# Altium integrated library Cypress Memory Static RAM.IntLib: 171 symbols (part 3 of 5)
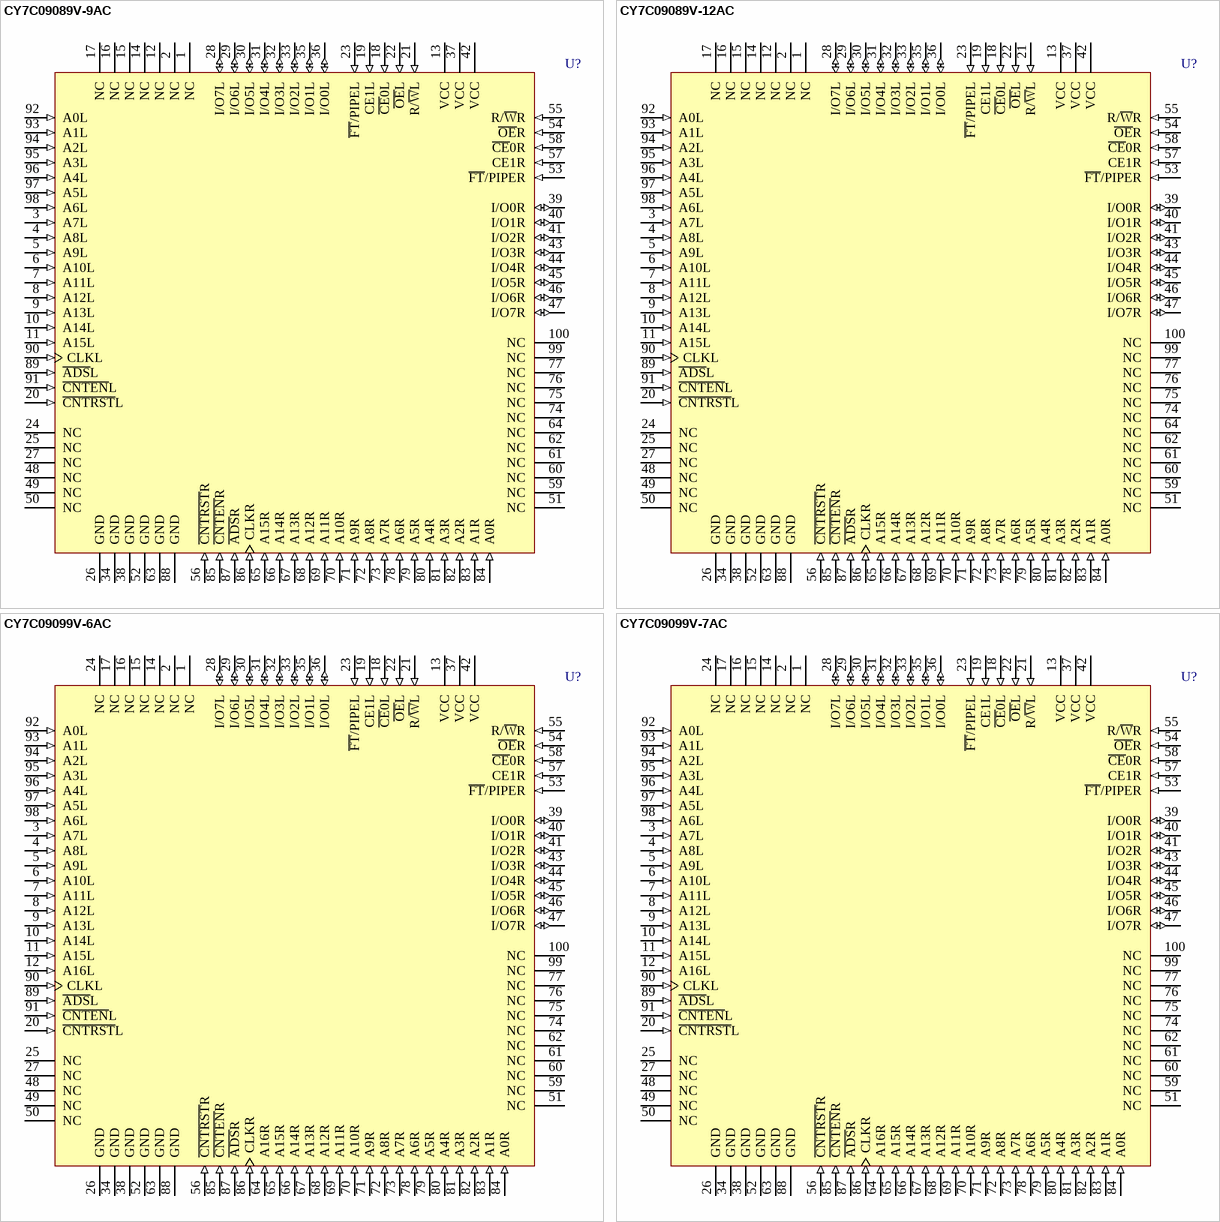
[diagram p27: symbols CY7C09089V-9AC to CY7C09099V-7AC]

## CY7C09099V-6AC
designator U?
3.3V 128K x 8 Synchronous Dual-Port Static RAM
footprint A100_N (Thin QFP, 100-Leads, Body 14x14mm, Pitch 0.5mm, IPC Medium Density)
footprint A100_L (Thin QFP, 100-Leads, Body 14x14mm, Pitch 0.5mm, IPC High Density)
footprint A100_M (Thin QFP, 100-Leads, Body 14x14mm, Pitch 0.5mm, IPC Low Density)
3D model CY7C09099V-A100 (100-Pin Thin Quad Flat Pack 0.5 mm Pitch)
pins: 1 NC, 2 NC, 3 A7L (in), 4 A8L (in), 5 A9L (in), 6 A10L (in), 7 A11L (in), 8 A12L (in), 9 A13L (in), 10 A14L (in), 11 A15L (in), 12 A16L (in), 13 VCC (power), 14 NC, 15 NC, 16 NC, 17 NC, 18 ~{CE}0L (in), 19 CE1L (in), 20 ~{CNTRST}L (in), 21 R/~{W}L (in), 22 ~{OE}L (in), 23 ~{FT}/PIPEL (in), 24 NC, 25 NC, 26 GND (power), 27 NC, 28 I/O7L (io), 29 I/O6L (io), 30 I/O5L (io), 31 I/O4L (io), 32 I/O3L (io), 33 I/O2L (io), 34 GND (power), 35 I/O1L (io), 36 I/O0L (io), 37 VCC (power), 38 GND (power), 39 I/O0R (io), 40 I/O1R (io), 41 I/O2R (io), 42 VCC (power), 43 I/O3R (io), 44 I/O4R (io), 45 I/O5R (io), 46 I/O6R (io), 47 I/O7R (io), 48 NC, 49 NC, 50 NC, 51 NC, 52 GND (power), 53 ~{FT}/PIPER (in), 54 ~{OE}R (in), 55 R/~{W}R (in), 56 ~{CNTRST}R (in), 57 CE1R (in), 58 ~{CE}0R (in), 59 NC, 60 NC, 61 NC, 62 NC, 63 GND (power), 64 A16R (in), 65 A15R (in), 66 A14R (in), 67 A13R (in), 68 A12R (in), 69 A11R (in), 70 A10R (in), 71 A9R (in), 72 A8R (in), 73 A7R (in), 74 NC, 75 NC, 76 NC, 77 NC, 78 A6R (in), 79 A5R (in), 80 A4R (in), 81 A3R (in), 82 A2R (in), 83 A1R (in), 84 A0R (in), 85 ~{CNTEN}R (in), 86 CLKR (in), 87 ~{ADS}R (in), 88 GND (power), 89 ~{ADS}L (in), 90 CLKL (in), 91 ~{CNTEN}L (in), 92 A0L (in), 93 A1L (in), 94 A2L (in), 95 A3L (in), 96 A4L (in), 97 A5L (in), 98 A6L (in), 99 NC, 100 NC

## CY7C09099V-7AC
designator U?
3.3V 128K x 8 Synchronous Dual-Port Static RAM
footprint A100_N (Thin QFP, 100-Leads, Body 14x14mm, Pitch 0.5mm, IPC Medium Density)
footprint A100_L (Thin QFP, 100-Leads, Body 14x14mm, Pitch 0.5mm, IPC High Density)
footprint A100_M (Thin QFP, 100-Leads, Body 14x14mm, Pitch 0.5mm, IPC Low Density)
3D model CY7C09099V-A100 (100-Pin Thin Quad Flat Pack 0.5 mm Pitch)
pins: 1 NC, 2 NC, 3 A7L (in), 4 A8L (in), 5 A9L (in), 6 A10L (in), 7 A11L (in), 8 A12L (in), 9 A13L (in), 10 A14L (in), 11 A15L (in), 12 A16L (in), 13 VCC (power), 14 NC, 15 NC, 16 NC, 17 NC, 18 ~{CE}0L (in), 19 CE1L (in), 20 ~{CNTRST}L (in), 21 R/~{W}L (in), 22 ~{OE}L (in), 23 ~{FT}/PIPEL (in), 24 NC, 25 NC, 26 GND (power), 27 NC, 28 I/O7L (io), 29 I/O6L (io), 30 I/O5L (io), 31 I/O4L (io), 32 I/O3L (io), 33 I/O2L (io), 34 GND (power), 35 I/O1L (io), 36 I/O0L (io), 37 VCC (power), 38 GND (power), 39 I/O0R (io), 40 I/O1R (io), 41 I/O2R (io), 42 VCC (power), 43 I/O3R (io), 44 I/O4R (io), 45 I/O5R (io), 46 I/O6R (io), 47 I/O7R (io), 48 NC, 49 NC, 50 NC, 51 NC, 52 GND (power), 53 ~{FT}/PIPER (in), 54 ~{OE}R (in), 55 R/~{W}R (in), 56 ~{CNTRST}R (in), 57 CE1R (in), 58 ~{CE}0R (in), 59 NC, 60 NC, 61 NC, 62 NC, 63 GND (power), 64 A16R (in), 65 A15R (in), 66 A14R (in), 67 A13R (in), 68 A12R (in), 69 A11R (in), 70 A10R (in), 71 A9R (in), 72 A8R (in), 73 A7R (in), 74 NC, 75 NC, 76 NC, 77 NC, 78 A6R (in), 79 A5R (in), 80 A4R (in), 81 A3R (in), 82 A2R (in), 83 A1R (in), 84 A0R (in), 85 ~{CNTEN}R (in), 86 CLKR (in), 87 ~{ADS}R (in), 88 GND (power), 89 ~{ADS}L (in), 90 CLKL (in), 91 ~{CNTEN}L (in), 92 A0L (in), 93 A1L (in), 94 A2L (in), 95 A3L (in), 96 A4L (in), 97 A5L (in), 98 A6L (in), 99 NC, 100 NC

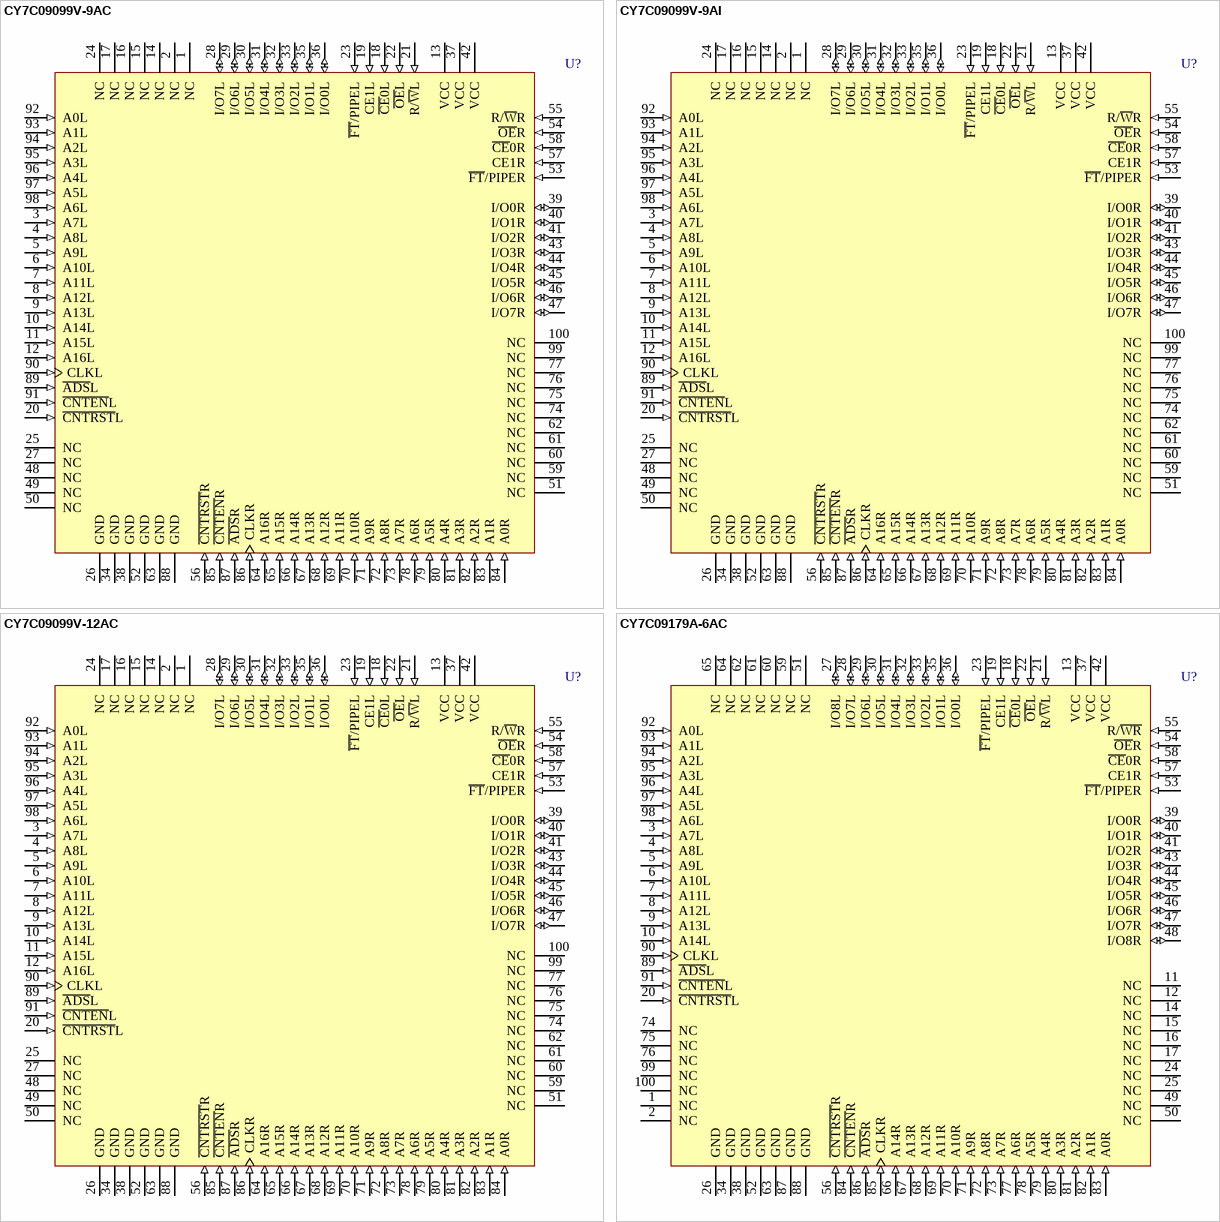
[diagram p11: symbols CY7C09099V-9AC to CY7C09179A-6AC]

## CY7C09099V-9AC
designator U?
3.3V 128K x 8 Synchronous Dual-Port Static RAM
footprint A100_N (Thin QFP, 100-Leads, Body 14x14mm, Pitch 0.5mm, IPC Medium Density)
footprint A100_L (Thin QFP, 100-Leads, Body 14x14mm, Pitch 0.5mm, IPC High Density)
footprint A100_M (Thin QFP, 100-Leads, Body 14x14mm, Pitch 0.5mm, IPC Low Density)
3D model CY7C09099V-A100 (100-Pin Thin Quad Flat Pack 0.5 mm Pitch)
pins: 1 NC, 2 NC, 3 A7L (in), 4 A8L (in), 5 A9L (in), 6 A10L (in), 7 A11L (in), 8 A12L (in), 9 A13L (in), 10 A14L (in), 11 A15L (in), 12 A16L (in), 13 VCC (power), 14 NC, 15 NC, 16 NC, 17 NC, 18 ~{CE}0L (in), 19 CE1L (in), 20 ~{CNTRST}L (in), 21 R/~{W}L (in), 22 ~{OE}L (in), 23 ~{FT}/PIPEL (in), 24 NC, 25 NC, 26 GND (power), 27 NC, 28 I/O7L (io), 29 I/O6L (io), 30 I/O5L (io), 31 I/O4L (io), 32 I/O3L (io), 33 I/O2L (io), 34 GND (power), 35 I/O1L (io), 36 I/O0L (io), 37 VCC (power), 38 GND (power), 39 I/O0R (io), 40 I/O1R (io), 41 I/O2R (io), 42 VCC (power), 43 I/O3R (io), 44 I/O4R (io), 45 I/O5R (io), 46 I/O6R (io), 47 I/O7R (io), 48 NC, 49 NC, 50 NC, 51 NC, 52 GND (power), 53 ~{FT}/PIPER (in), 54 ~{OE}R (in), 55 R/~{W}R (in), 56 ~{CNTRST}R (in), 57 CE1R (in), 58 ~{CE}0R (in), 59 NC, 60 NC, 61 NC, 62 NC, 63 GND (power), 64 A16R (in), 65 A15R (in), 66 A14R (in), 67 A13R (in), 68 A12R (in), 69 A11R (in), 70 A10R (in), 71 A9R (in), 72 A8R (in), 73 A7R (in), 74 NC, 75 NC, 76 NC, 77 NC, 78 A6R (in), 79 A5R (in), 80 A4R (in), 81 A3R (in), 82 A2R (in), 83 A1R (in), 84 A0R (in), 85 ~{CNTEN}R (in), 86 CLKR (in), 87 ~{ADS}R (in), 88 GND (power), 89 ~{ADS}L (in), 90 CLKL (in), 91 ~{CNTEN}L (in), 92 A0L (in), 93 A1L (in), 94 A2L (in), 95 A3L (in), 96 A4L (in), 97 A5L (in), 98 A6L (in), 99 NC, 100 NC

## CY7C09099V-9AI
designator U?
3.3V 128K x 8 Synchronous Dual-Port Static RAM
footprint A100_N (Thin QFP, 100-Leads, Body 14x14mm, Pitch 0.5mm, IPC Medium Density)
footprint A100_L (Thin QFP, 100-Leads, Body 14x14mm, Pitch 0.5mm, IPC High Density)
footprint A100_M (Thin QFP, 100-Leads, Body 14x14mm, Pitch 0.5mm, IPC Low Density)
3D model CY7C09099V-A100 (100-Pin Thin Quad Flat Pack 0.5 mm Pitch)
pins: 1 NC, 2 NC, 3 A7L (in), 4 A8L (in), 5 A9L (in), 6 A10L (in), 7 A11L (in), 8 A12L (in), 9 A13L (in), 10 A14L (in), 11 A15L (in), 12 A16L (in), 13 VCC (power), 14 NC, 15 NC, 16 NC, 17 NC, 18 ~{CE}0L (in), 19 CE1L (in), 20 ~{CNTRST}L (in), 21 R/~{W}L (in), 22 ~{OE}L (in), 23 ~{FT}/PIPEL (in), 24 NC, 25 NC, 26 GND (power), 27 NC, 28 I/O7L (io), 29 I/O6L (io), 30 I/O5L (io), 31 I/O4L (io), 32 I/O3L (io), 33 I/O2L (io), 34 GND (power), 35 I/O1L (io), 36 I/O0L (io), 37 VCC (power), 38 GND (power), 39 I/O0R (io), 40 I/O1R (io), 41 I/O2R (io), 42 VCC (power), 43 I/O3R (io), 44 I/O4R (io), 45 I/O5R (io), 46 I/O6R (io), 47 I/O7R (io), 48 NC, 49 NC, 50 NC, 51 NC, 52 GND (power), 53 ~{FT}/PIPER (in), 54 ~{OE}R (in), 55 R/~{W}R (in), 56 ~{CNTRST}R (in), 57 CE1R (in), 58 ~{CE}0R (in), 59 NC, 60 NC, 61 NC, 62 NC, 63 GND (power), 64 A16R (in), 65 A15R (in), 66 A14R (in), 67 A13R (in), 68 A12R (in), 69 A11R (in), 70 A10R (in), 71 A9R (in), 72 A8R (in), 73 A7R (in), 74 NC, 75 NC, 76 NC, 77 NC, 78 A6R (in), 79 A5R (in), 80 A4R (in), 81 A3R (in), 82 A2R (in), 83 A1R (in), 84 A0R (in), 85 ~{CNTEN}R (in), 86 CLKR (in), 87 ~{ADS}R (in), 88 GND (power), 89 ~{ADS}L (in), 90 CLKL (in), 91 ~{CNTEN}L (in), 92 A0L (in), 93 A1L (in), 94 A2L (in), 95 A3L (in), 96 A4L (in), 97 A5L (in), 98 A6L (in), 99 NC, 100 NC

## CY7C09099V-12AC
designator U?
3.3V 128K x 8 Synchronous Dual-Port Static RAM
footprint A100_N (Thin QFP, 100-Leads, Body 14x14mm, Pitch 0.5mm, IPC Medium Density)
footprint A100_L (Thin QFP, 100-Leads, Body 14x14mm, Pitch 0.5mm, IPC High Density)
footprint A100_M (Thin QFP, 100-Leads, Body 14x14mm, Pitch 0.5mm, IPC Low Density)
3D model CY7C09099V-A100 (100-Pin Thin Quad Flat Pack 0.5 mm Pitch)
pins: 1 NC, 2 NC, 3 A7L (in), 4 A8L (in), 5 A9L (in), 6 A10L (in), 7 A11L (in), 8 A12L (in), 9 A13L (in), 10 A14L (in), 11 A15L (in), 12 A16L (in), 13 VCC (power), 14 NC, 15 NC, 16 NC, 17 NC, 18 ~{CE}0L (in), 19 CE1L (in), 20 ~{CNTRST}L (in), 21 R/~{W}L (in), 22 ~{OE}L (in), 23 ~{FT}/PIPEL (in), 24 NC, 25 NC, 26 GND (power), 27 NC, 28 I/O7L (io), 29 I/O6L (io), 30 I/O5L (io), 31 I/O4L (io), 32 I/O3L (io), 33 I/O2L (io), 34 GND (power), 35 I/O1L (io), 36 I/O0L (io), 37 VCC (power), 38 GND (power), 39 I/O0R (io), 40 I/O1R (io), 41 I/O2R (io), 42 VCC (power), 43 I/O3R (io), 44 I/O4R (io), 45 I/O5R (io), 46 I/O6R (io), 47 I/O7R (io), 48 NC, 49 NC, 50 NC, 51 NC, 52 GND (power), 53 ~{FT}/PIPER (in), 54 ~{OE}R (in), 55 R/~{W}R (in), 56 ~{CNTRST}R (in), 57 CE1R (in), 58 ~{CE}0R (in), 59 NC, 60 NC, 61 NC, 62 NC, 63 GND (power), 64 A16R (in), 65 A15R (in), 66 A14R (in), 67 A13R (in), 68 A12R (in), 69 A11R (in), 70 A10R (in), 71 A9R (in), 72 A8R (in), 73 A7R (in), 74 NC, 75 NC, 76 NC, 77 NC, 78 A6R (in), 79 A5R (in), 80 A4R (in), 81 A3R (in), 82 A2R (in), 83 A1R (in), 84 A0R (in), 85 ~{CNTEN}R (in), 86 CLKR (in), 87 ~{ADS}R (in), 88 GND (power), 89 ~{ADS}L (in), 90 CLKL (in), 91 ~{CNTEN}L (in), 92 A0L (in), 93 A1L (in), 94 A2L (in), 95 A3L (in), 96 A4L (in), 97 A5L (in), 98 A6L (in), 99 NC, 100 NC

## CY7C09179A-6AC
designator U?
32K x 9 Synchronous Dual-Port RAM
footprint A100_N (Thin QFP, 100-Leads, Body 14x14mm, Pitch 0.5mm, IPC Medium Density)
footprint A100_L (Thin QFP, 100-Leads, Body 14x14mm, Pitch 0.5mm, IPC High Density)
footprint A100_M (Thin QFP, 100-Leads, Body 14x14mm, Pitch 0.5mm, IPC Low Density)
3D model CY7C09179A-A100 (100-Pin Thin Quad Flat Pack 0.5 mm Pitch)
pins: 1 NC, 2 NC, 3 A7L (in), 4 A8L (in), 5 A9L (in), 6 A10L (in), 7 A11L (in), 8 A12L (in), 9 A13L (in), 10 A14L (in), 11 NC, 12 NC, 13 VCC (power), 14 NC, 15 NC, 16 NC, 17 NC, 18 ~{CE}0L (in), 19 CE1L (in), 20 ~{CNTRST}L (in), 21 R/~{W}L (in), 22 ~{OE}L (in), 23 ~{FT}/PIPEL (in), 24 NC, 25 NC, 26 GND (power), 27 I/O8L (io), 28 I/O7L (io), 29 I/O6L (io), 30 I/O5L (io), 31 I/O4L (io), 32 I/O3L (io), 33 I/O2L (io), 34 GND (power), 35 I/O1L (io), 36 I/O0L (io), 37 VCC (power), 38 GND (power), 39 I/O0R (io), 40 I/O1R (io), 41 I/O2R (io), 42 VCC (power), 43 I/O3R (io), 44 I/O4R (io), 45 I/O5R (io), 46 I/O6R (io), 47 I/O7R (io), 48 I/O8R (io), 49 NC, 50 NC, 51 NC, 52 GND (power), 53 ~{FT}/PIPER (in), 54 ~{OE}R (in), 55 R/~{WR} (in), 56 ~{CNTRST}R (in), 57 CE1R (in), 58 ~{CE}0R (in), 59 NC, 60 NC, 61 NC, 62 NC, 63 GND (power), 64 NC, 65 NC, 66 A14R (in), 67 A13R (in), 68 A12R (in), 69 A11R (in), 70 A10R (in), 71 A9R (in), 72 A8R (in), 73 A7R (in), 74 NC, 75 NC, 76 NC, 77 A6R (in), 78 A5R (in), 79 A4R (in), 80 A3R (in), 81 A2R (in), 82 A1R (in), 83 A0R (in), 84 ~{CNTEN}R (in), 85 CLKR (in), 86 ~{ADS}R (in), 87 GND (power), 88 GND (power), 89 ~{ADS}L (in), 90 CLKL (in), 91 ~{CNTEN}L (in), 92 A0L (in), 93 A1L (in), 94 A2L (in), 95 A3L (in), 96 A4L (in), 97 A5L (in), 98 A6L (in), 99 NC, 100 NC

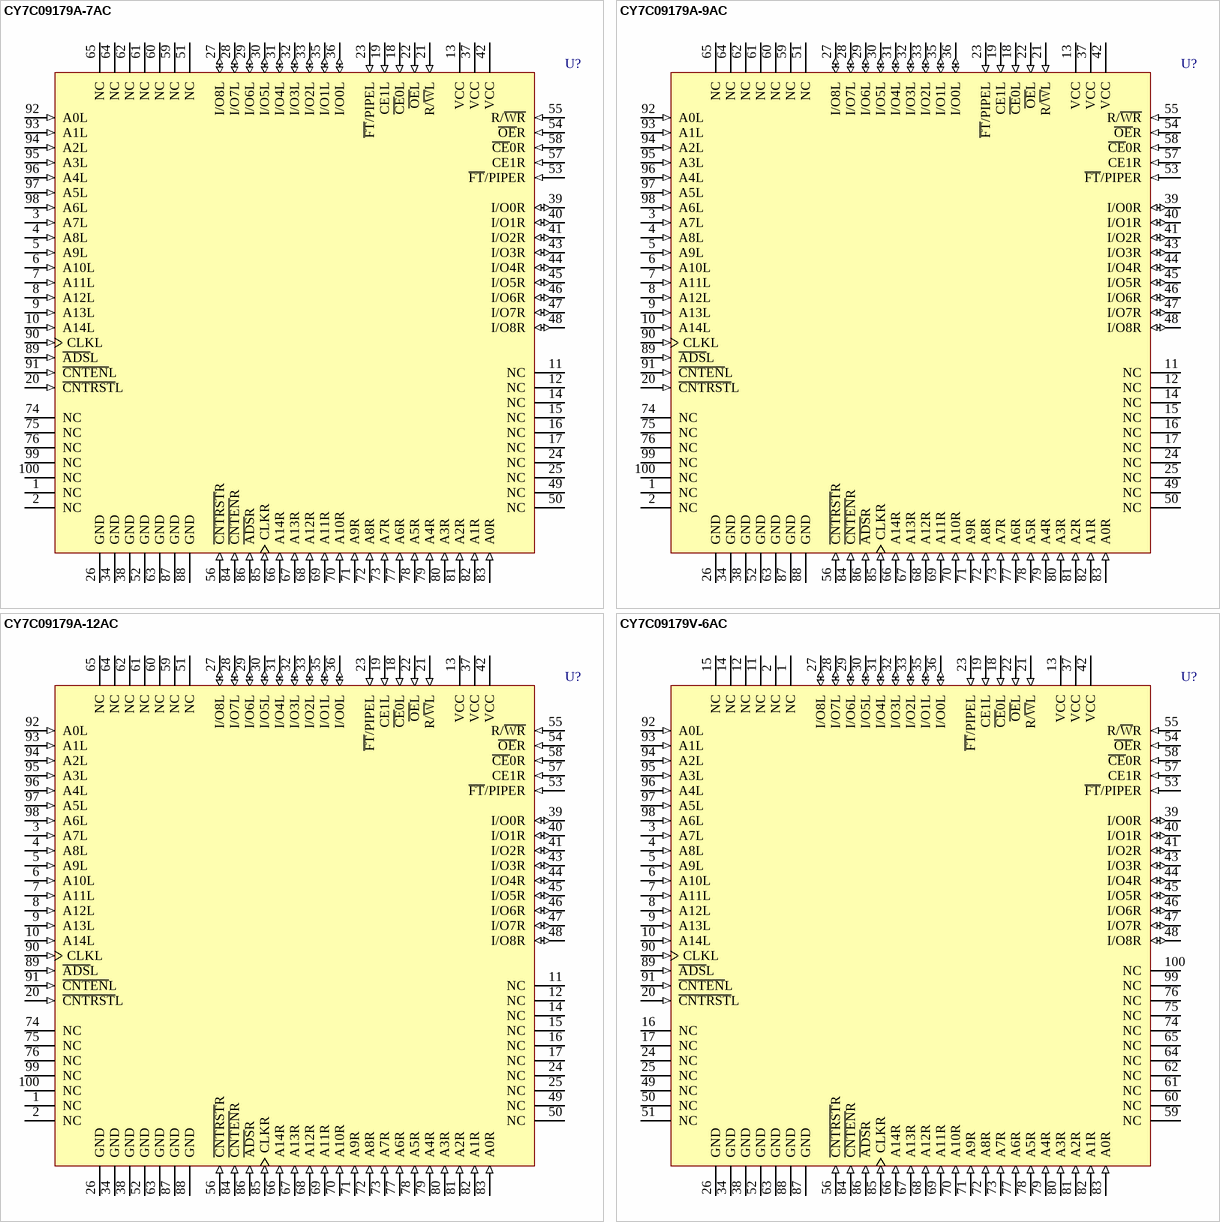
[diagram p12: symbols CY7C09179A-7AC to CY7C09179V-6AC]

## CY7C09179A-7AC
designator U?
32K x 9 Synchronous Dual-Port RAM
footprint A100_N (Thin QFP, 100-Leads, Body 14x14mm, Pitch 0.5mm, IPC Medium Density)
footprint A100_L (Thin QFP, 100-Leads, Body 14x14mm, Pitch 0.5mm, IPC High Density)
footprint A100_M (Thin QFP, 100-Leads, Body 14x14mm, Pitch 0.5mm, IPC Low Density)
3D model CY7C09179A-A100 (100-Pin Thin Quad Flat Pack 0.5 mm Pitch)
pins: 1 NC, 2 NC, 3 A7L (in), 4 A8L (in), 5 A9L (in), 6 A10L (in), 7 A11L (in), 8 A12L (in), 9 A13L (in), 10 A14L (in), 11 NC, 12 NC, 13 VCC (power), 14 NC, 15 NC, 16 NC, 17 NC, 18 ~{CE}0L (in), 19 CE1L (in), 20 ~{CNTRST}L (in), 21 R/~{W}L (in), 22 ~{OE}L (in), 23 ~{FT}/PIPEL (in), 24 NC, 25 NC, 26 GND (power), 27 I/O8L (io), 28 I/O7L (io), 29 I/O6L (io), 30 I/O5L (io), 31 I/O4L (io), 32 I/O3L (io), 33 I/O2L (io), 34 GND (power), 35 I/O1L (io), 36 I/O0L (io), 37 VCC (power), 38 GND (power), 39 I/O0R (io), 40 I/O1R (io), 41 I/O2R (io), 42 VCC (power), 43 I/O3R (io), 44 I/O4R (io), 45 I/O5R (io), 46 I/O6R (io), 47 I/O7R (io), 48 I/O8R (io), 49 NC, 50 NC, 51 NC, 52 GND (power), 53 ~{FT}/PIPER (in), 54 ~{OE}R (in), 55 R/~{WR} (in), 56 ~{CNTRST}R (in), 57 CE1R (in), 58 ~{CE}0R (in), 59 NC, 60 NC, 61 NC, 62 NC, 63 GND (power), 64 NC, 65 NC, 66 A14R (in), 67 A13R (in), 68 A12R (in), 69 A11R (in), 70 A10R (in), 71 A9R (in), 72 A8R (in), 73 A7R (in), 74 NC, 75 NC, 76 NC, 77 A6R (in), 78 A5R (in), 79 A4R (in), 80 A3R (in), 81 A2R (in), 82 A1R (in), 83 A0R (in), 84 ~{CNTEN}R (in), 85 CLKR (in), 86 ~{ADS}R (in), 87 GND (power), 88 GND (power), 89 ~{ADS}L (in), 90 CLKL (in), 91 ~{CNTEN}L (in), 92 A0L (in), 93 A1L (in), 94 A2L (in), 95 A3L (in), 96 A4L (in), 97 A5L (in), 98 A6L (in), 99 NC, 100 NC

## CY7C09179A-9AC
designator U?
32K x 9 Synchronous Dual-Port RAM
footprint A100_N (Thin QFP, 100-Leads, Body 14x14mm, Pitch 0.5mm, IPC Medium Density)
footprint A100_L (Thin QFP, 100-Leads, Body 14x14mm, Pitch 0.5mm, IPC High Density)
footprint A100_M (Thin QFP, 100-Leads, Body 14x14mm, Pitch 0.5mm, IPC Low Density)
3D model CY7C09179A-A100 (100-Pin Thin Quad Flat Pack 0.5 mm Pitch)
pins: 1 NC, 2 NC, 3 A7L (in), 4 A8L (in), 5 A9L (in), 6 A10L (in), 7 A11L (in), 8 A12L (in), 9 A13L (in), 10 A14L (in), 11 NC, 12 NC, 13 VCC (power), 14 NC, 15 NC, 16 NC, 17 NC, 18 ~{CE}0L (in), 19 CE1L (in), 20 ~{CNTRST}L (in), 21 R/~{W}L (in), 22 ~{OE}L (in), 23 ~{FT}/PIPEL (in), 24 NC, 25 NC, 26 GND (power), 27 I/O8L (io), 28 I/O7L (io), 29 I/O6L (io), 30 I/O5L (io), 31 I/O4L (io), 32 I/O3L (io), 33 I/O2L (io), 34 GND (power), 35 I/O1L (io), 36 I/O0L (io), 37 VCC (power), 38 GND (power), 39 I/O0R (io), 40 I/O1R (io), 41 I/O2R (io), 42 VCC (power), 43 I/O3R (io), 44 I/O4R (io), 45 I/O5R (io), 46 I/O6R (io), 47 I/O7R (io), 48 I/O8R (io), 49 NC, 50 NC, 51 NC, 52 GND (power), 53 ~{FT}/PIPER (in), 54 ~{OE}R (in), 55 R/~{WR} (in), 56 ~{CNTRST}R (in), 57 CE1R (in), 58 ~{CE}0R (in), 59 NC, 60 NC, 61 NC, 62 NC, 63 GND (power), 64 NC, 65 NC, 66 A14R (in), 67 A13R (in), 68 A12R (in), 69 A11R (in), 70 A10R (in), 71 A9R (in), 72 A8R (in), 73 A7R (in), 74 NC, 75 NC, 76 NC, 77 A6R (in), 78 A5R (in), 79 A4R (in), 80 A3R (in), 81 A2R (in), 82 A1R (in), 83 A0R (in), 84 ~{CNTEN}R (in), 85 CLKR (in), 86 ~{ADS}R (in), 87 GND (power), 88 GND (power), 89 ~{ADS}L (in), 90 CLKL (in), 91 ~{CNTEN}L (in), 92 A0L (in), 93 A1L (in), 94 A2L (in), 95 A3L (in), 96 A4L (in), 97 A5L (in), 98 A6L (in), 99 NC, 100 NC

## CY7C09179A-12AC
designator U?
32K x 9 Synchronous Dual-Port RAM
footprint A100_N (Thin QFP, 100-Leads, Body 14x14mm, Pitch 0.5mm, IPC Medium Density)
footprint A100_L (Thin QFP, 100-Leads, Body 14x14mm, Pitch 0.5mm, IPC High Density)
footprint A100_M (Thin QFP, 100-Leads, Body 14x14mm, Pitch 0.5mm, IPC Low Density)
3D model CY7C09179A-A100 (100-Pin Thin Quad Flat Pack 0.5 mm Pitch)
pins: 1 NC, 2 NC, 3 A7L (in), 4 A8L (in), 5 A9L (in), 6 A10L (in), 7 A11L (in), 8 A12L (in), 9 A13L (in), 10 A14L (in), 11 NC, 12 NC, 13 VCC (power), 14 NC, 15 NC, 16 NC, 17 NC, 18 ~{CE}0L (in), 19 CE1L (in), 20 ~{CNTRST}L (in), 21 R/~{W}L (in), 22 ~{OE}L (in), 23 ~{FT}/PIPEL (in), 24 NC, 25 NC, 26 GND (power), 27 I/O8L (io), 28 I/O7L (io), 29 I/O6L (io), 30 I/O5L (io), 31 I/O4L (io), 32 I/O3L (io), 33 I/O2L (io), 34 GND (power), 35 I/O1L (io), 36 I/O0L (io), 37 VCC (power), 38 GND (power), 39 I/O0R (io), 40 I/O1R (io), 41 I/O2R (io), 42 VCC (power), 43 I/O3R (io), 44 I/O4R (io), 45 I/O5R (io), 46 I/O6R (io), 47 I/O7R (io), 48 I/O8R (io), 49 NC, 50 NC, 51 NC, 52 GND (power), 53 ~{FT}/PIPER (in), 54 ~{OE}R (in), 55 R/~{WR} (in), 56 ~{CNTRST}R (in), 57 CE1R (in), 58 ~{CE}0R (in), 59 NC, 60 NC, 61 NC, 62 NC, 63 GND (power), 64 NC, 65 NC, 66 A14R (in), 67 A13R (in), 68 A12R (in), 69 A11R (in), 70 A10R (in), 71 A9R (in), 72 A8R (in), 73 A7R (in), 74 NC, 75 NC, 76 NC, 77 A6R (in), 78 A5R (in), 79 A4R (in), 80 A3R (in), 81 A2R (in), 82 A1R (in), 83 A0R (in), 84 ~{CNTEN}R (in), 85 CLKR (in), 86 ~{ADS}R (in), 87 GND (power), 88 GND (power), 89 ~{ADS}L (in), 90 CLKL (in), 91 ~{CNTEN}L (in), 92 A0L (in), 93 A1L (in), 94 A2L (in), 95 A3L (in), 96 A4L (in), 97 A5L (in), 98 A6L (in), 99 NC, 100 NC

## CY7C09179V-6AC
designator U?
3.3V 32K x 9 Synchronous Dual-Port Static RAM
footprint A100_N (Thin QFP, 100-Leads, Body 14x14mm, Pitch 0.5mm, IPC Medium Density)
footprint A100_L (Thin QFP, 100-Leads, Body 14x14mm, Pitch 0.5mm, IPC High Density)
footprint A100_M (Thin QFP, 100-Leads, Body 14x14mm, Pitch 0.5mm, IPC Low Density)
3D model CY7C09179V-A100 (100-Pin Thin Quad Flat Pack 0.5 mm Pitch)
pins: 1 NC, 2 NC, 3 A7L (in), 4 A8L (in), 5 A9L (in), 6 A10L (in), 7 A11L (in), 8 A12L (in), 9 A13L (in), 10 A14L (in), 11 NC, 12 NC, 13 VCC (power), 14 NC, 15 NC, 16 NC, 17 NC, 18 ~{CE}0L (in), 19 CE1L (in), 20 ~{CNTRST}L (in), 21 R/~{W}L (in), 22 ~{OE}L (in), 23 ~{FT}/PIPEL (in), 24 NC, 25 NC, 26 GND (power), 27 I/O8L (io), 28 I/O7L (io), 29 I/O6L (io), 30 I/O5L (io), 31 I/O4L (io), 32 I/O3L (io), 33 I/O2L (io), 34 GND (power), 35 I/O1L (io), 36 I/O0L (io), 37 VCC (power), 38 GND (power), 39 I/O0R (io), 40 I/O1R (io), 41 I/O2R (io), 42 VCC (power), 43 I/O3R (io), 44 I/O4R (io), 45 I/O5R (io), 46 I/O6R (io), 47 I/O7R (io), 48 I/O8R (io), 49 NC, 50 NC, 51 NC, 52 GND (power), 53 ~{FT}/PIPER (in), 54 ~{OE}R (in), 55 R/~{W}R (in), 56 ~{CNTRST}R (in), 57 CE1R (in), 58 ~{CE}0R (in), 59 NC, 60 NC, 61 NC, 62 NC, 63 GND (power), 64 NC, 65 NC, 66 A14R (in), 67 A13R (in), 68 A12R (in), 69 A11R (in), 70 A10R (in), 71 A9R (in), 72 A8R (in), 73 A7R (in), 74 NC, 75 NC, 76 NC, 77 A6R (in), 78 A5R (in), 79 A4R (in), 80 A3R (in), 81 A2R (in), 82 A1R (in), 83 A0R (in), 84 ~{CNTEN}R (in), 85 CLKR (in), 86 ~{ADS}R (in), 87 GND (power), 88 GND (power), 89 ~{ADS}L (in), 90 CLKL (in), 91 ~{CNTEN}L (in), 92 A0L (in), 93 A1L (in), 94 A2L (in), 95 A3L (in), 96 A4L (in), 97 A5L (in), 98 A6L (in), 99 NC, 100 NC

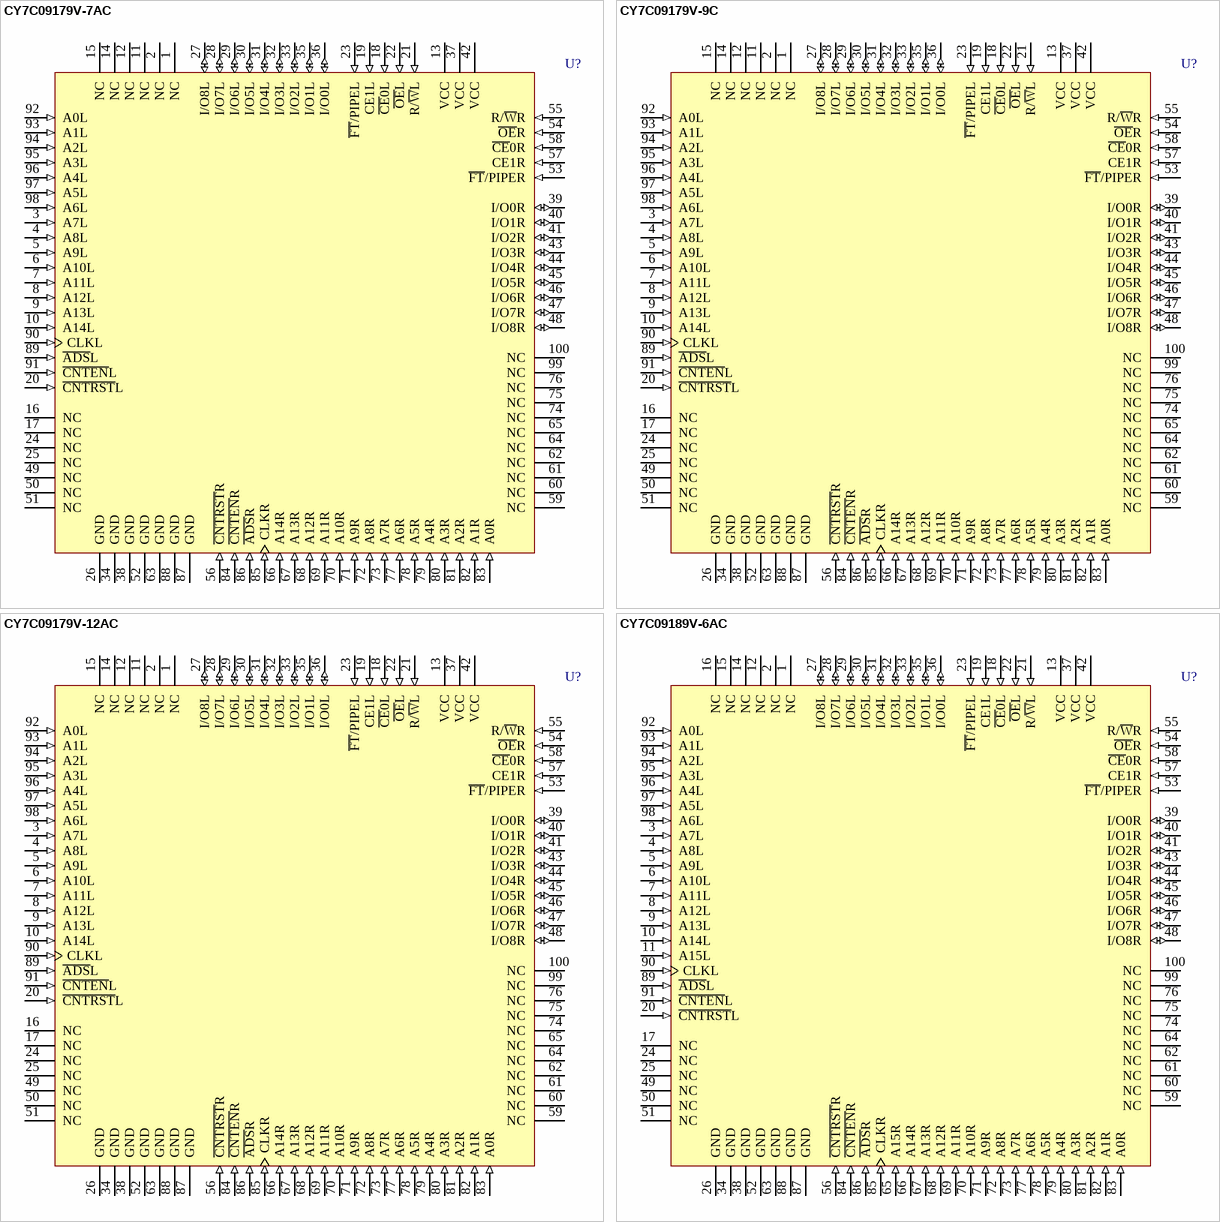
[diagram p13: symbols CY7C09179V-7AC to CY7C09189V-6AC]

## CY7C09179V-7AC
designator U?
3.3V 32K x 9 Synchronous Dual-Port Static RAM
footprint A100_N (Thin QFP, 100-Leads, Body 14x14mm, Pitch 0.5mm, IPC Medium Density)
footprint A100_L (Thin QFP, 100-Leads, Body 14x14mm, Pitch 0.5mm, IPC High Density)
footprint A100_M (Thin QFP, 100-Leads, Body 14x14mm, Pitch 0.5mm, IPC Low Density)
3D model CY7C09179V-A100 (100-Pin Thin Quad Flat Pack 0.5 mm Pitch)
pins: 1 NC, 2 NC, 3 A7L (in), 4 A8L (in), 5 A9L (in), 6 A10L (in), 7 A11L (in), 8 A12L (in), 9 A13L (in), 10 A14L (in), 11 NC, 12 NC, 13 VCC (power), 14 NC, 15 NC, 16 NC, 17 NC, 18 ~{CE}0L (in), 19 CE1L (in), 20 ~{CNTRST}L (in), 21 R/~{W}L (in), 22 ~{OE}L (in), 23 ~{FT}/PIPEL (in), 24 NC, 25 NC, 26 GND (power), 27 I/O8L (io), 28 I/O7L (io), 29 I/O6L (io), 30 I/O5L (io), 31 I/O4L (io), 32 I/O3L (io), 33 I/O2L (io), 34 GND (power), 35 I/O1L (io), 36 I/O0L (io), 37 VCC (power), 38 GND (power), 39 I/O0R (io), 40 I/O1R (io), 41 I/O2R (io), 42 VCC (power), 43 I/O3R (io), 44 I/O4R (io), 45 I/O5R (io), 46 I/O6R (io), 47 I/O7R (io), 48 I/O8R (io), 49 NC, 50 NC, 51 NC, 52 GND (power), 53 ~{FT}/PIPER (in), 54 ~{OE}R (in), 55 R/~{W}R (in), 56 ~{CNTRST}R (in), 57 CE1R (in), 58 ~{CE}0R (in), 59 NC, 60 NC, 61 NC, 62 NC, 63 GND (power), 64 NC, 65 NC, 66 A14R (in), 67 A13R (in), 68 A12R (in), 69 A11R (in), 70 A10R (in), 71 A9R (in), 72 A8R (in), 73 A7R (in), 74 NC, 75 NC, 76 NC, 77 A6R (in), 78 A5R (in), 79 A4R (in), 80 A3R (in), 81 A2R (in), 82 A1R (in), 83 A0R (in), 84 ~{CNTEN}R (in), 85 CLKR (in), 86 ~{ADS}R (in), 87 GND (power), 88 GND (power), 89 ~{ADS}L (in), 90 CLKL (in), 91 ~{CNTEN}L (in), 92 A0L (in), 93 A1L (in), 94 A2L (in), 95 A3L (in), 96 A4L (in), 97 A5L (in), 98 A6L (in), 99 NC, 100 NC

## CY7C09179V-9C
designator U?
3.3V 32K x 9 Synchronous Dual-Port Static RAM
footprint A100_N (Thin QFP, 100-Leads, Body 14x14mm, Pitch 0.5mm, IPC Medium Density)
footprint A100_L (Thin QFP, 100-Leads, Body 14x14mm, Pitch 0.5mm, IPC High Density)
footprint A100_M (Thin QFP, 100-Leads, Body 14x14mm, Pitch 0.5mm, IPC Low Density)
3D model CY7C09179V-A100 (100-Pin Thin Quad Flat Pack 0.5 mm Pitch)
pins: 1 NC, 2 NC, 3 A7L (in), 4 A8L (in), 5 A9L (in), 6 A10L (in), 7 A11L (in), 8 A12L (in), 9 A13L (in), 10 A14L (in), 11 NC, 12 NC, 13 VCC (power), 14 NC, 15 NC, 16 NC, 17 NC, 18 ~{CE}0L (in), 19 CE1L (in), 20 ~{CNTRST}L (in), 21 R/~{W}L (in), 22 ~{OE}L (in), 23 ~{FT}/PIPEL (in), 24 NC, 25 NC, 26 GND (power), 27 I/O8L (io), 28 I/O7L (io), 29 I/O6L (io), 30 I/O5L (io), 31 I/O4L (io), 32 I/O3L (io), 33 I/O2L (io), 34 GND (power), 35 I/O1L (io), 36 I/O0L (io), 37 VCC (power), 38 GND (power), 39 I/O0R (io), 40 I/O1R (io), 41 I/O2R (io), 42 VCC (power), 43 I/O3R (io), 44 I/O4R (io), 45 I/O5R (io), 46 I/O6R (io), 47 I/O7R (io), 48 I/O8R (io), 49 NC, 50 NC, 51 NC, 52 GND (power), 53 ~{FT}/PIPER (in), 54 ~{OE}R (in), 55 R/~{W}R (in), 56 ~{CNTRST}R (in), 57 CE1R (in), 58 ~{CE}0R (in), 59 NC, 60 NC, 61 NC, 62 NC, 63 GND (power), 64 NC, 65 NC, 66 A14R (in), 67 A13R (in), 68 A12R (in), 69 A11R (in), 70 A10R (in), 71 A9R (in), 72 A8R (in), 73 A7R (in), 74 NC, 75 NC, 76 NC, 77 A6R (in), 78 A5R (in), 79 A4R (in), 80 A3R (in), 81 A2R (in), 82 A1R (in), 83 A0R (in), 84 ~{CNTEN}R (in), 85 CLKR (in), 86 ~{ADS}R (in), 87 GND (power), 88 GND (power), 89 ~{ADS}L (in), 90 CLKL (in), 91 ~{CNTEN}L (in), 92 A0L (in), 93 A1L (in), 94 A2L (in), 95 A3L (in), 96 A4L (in), 97 A5L (in), 98 A6L (in), 99 NC, 100 NC

## CY7C09179V-12AC
designator U?
3.3V 32K x 9 Synchronous Dual-Port Static RAM
footprint A100_N (Thin QFP, 100-Leads, Body 14x14mm, Pitch 0.5mm, IPC Medium Density)
footprint A100_L (Thin QFP, 100-Leads, Body 14x14mm, Pitch 0.5mm, IPC High Density)
footprint A100_M (Thin QFP, 100-Leads, Body 14x14mm, Pitch 0.5mm, IPC Low Density)
3D model CY7C09179V-A100 (100-Pin Thin Quad Flat Pack 0.5 mm Pitch)
pins: 1 NC, 2 NC, 3 A7L (in), 4 A8L (in), 5 A9L (in), 6 A10L (in), 7 A11L (in), 8 A12L (in), 9 A13L (in), 10 A14L (in), 11 NC, 12 NC, 13 VCC (power), 14 NC, 15 NC, 16 NC, 17 NC, 18 ~{CE}0L (in), 19 CE1L (in), 20 ~{CNTRST}L (in), 21 R/~{W}L (in), 22 ~{OE}L (in), 23 ~{FT}/PIPEL (in), 24 NC, 25 NC, 26 GND (power), 27 I/O8L (io), 28 I/O7L (io), 29 I/O6L (io), 30 I/O5L (io), 31 I/O4L (io), 32 I/O3L (io), 33 I/O2L (io), 34 GND (power), 35 I/O1L (io), 36 I/O0L (io), 37 VCC (power), 38 GND (power), 39 I/O0R (io), 40 I/O1R (io), 41 I/O2R (io), 42 VCC (power), 43 I/O3R (io), 44 I/O4R (io), 45 I/O5R (io), 46 I/O6R (io), 47 I/O7R (io), 48 I/O8R (io), 49 NC, 50 NC, 51 NC, 52 GND (power), 53 ~{FT}/PIPER (in), 54 ~{OE}R (in), 55 R/~{W}R (in), 56 ~{CNTRST}R (in), 57 CE1R (in), 58 ~{CE}0R (in), 59 NC, 60 NC, 61 NC, 62 NC, 63 GND (power), 64 NC, 65 NC, 66 A14R (in), 67 A13R (in), 68 A12R (in), 69 A11R (in), 70 A10R (in), 71 A9R (in), 72 A8R (in), 73 A7R (in), 74 NC, 75 NC, 76 NC, 77 A6R (in), 78 A5R (in), 79 A4R (in), 80 A3R (in), 81 A2R (in), 82 A1R (in), 83 A0R (in), 84 ~{CNTEN}R (in), 85 CLKR (in), 86 ~{ADS}R (in), 87 GND (power), 88 GND (power), 89 ~{ADS}L (in), 90 CLKL (in), 91 ~{CNTEN}L (in), 92 A0L (in), 93 A1L (in), 94 A2L (in), 95 A3L (in), 96 A4L (in), 97 A5L (in), 98 A6L (in), 99 NC, 100 NC

## CY7C09189V-6AC
designator U?
3.3V 64K x 9 Synchronous Dual-Port Static RAM
footprint A100_N (Thin QFP, 100-Leads, Body 14x14mm, Pitch 0.5mm, IPC Medium Density)
footprint A100_L (Thin QFP, 100-Leads, Body 14x14mm, Pitch 0.5mm, IPC High Density)
footprint A100_M (Thin QFP, 100-Leads, Body 14x14mm, Pitch 0.5mm, IPC Low Density)
3D model CY7C09189V-A100 (100-Pin Thin Quad Flat Pack 0.5 mm Pitch)
pins: 1 NC, 2 NC, 3 A7L (in), 4 A8L (in), 5 A9L (in), 6 A10L (in), 7 A11L (in), 8 A12L (in), 9 A13L (in), 10 A14L (in), 11 A15L (in), 12 NC, 13 VCC (power), 14 NC, 15 NC, 16 NC, 17 NC, 18 ~{CE}0L (in), 19 CE1L (in), 20 ~{CNTRST}L (in), 21 R/~{W}L (in), 22 ~{OE}L (in), 23 ~{FT}/PIPEL (in), 24 NC, 25 NC, 26 GND (power), 27 I/O8L (io), 28 I/O7L (io), 29 I/O6L (io), 30 I/O5L (io), 31 I/O4L (io), 32 I/O3L (io), 33 I/O2L (io), 34 GND (power), 35 I/O1L (io), 36 I/O0L (io), 37 VCC (power), 38 GND (power), 39 I/O0R (io), 40 I/O1R (io), 41 I/O2R (io), 42 VCC (power), 43 I/O3R (io), 44 I/O4R (io), 45 I/O5R (io), 46 I/O6R (io), 47 I/O7R (io), 48 I/O8R (io), 49 NC, 50 NC, 51 NC, 52 GND (power), 53 ~{FT}/PIPER (in), 54 ~{OE}R (in), 55 R/~{W}R (in), 56 ~{CNTRST}R (in), 57 CE1R (in), 58 ~{CE}0R (in), 59 NC, 60 NC, 61 NC, 62 NC, 63 GND (power), 64 NC, 65 A15R (in), 66 A14R (in), 67 A13R (in), 68 A12R (in), 69 A11R (in), 70 A10R (in), 71 A9R (in), 72 A8R (in), 73 A7R (in), 74 NC, 75 NC, 76 NC, 77 A6R (in), 78 A5R (in), 79 A4R (in), 80 A3R (in), 81 A2R (in), 82 A1R (in), 83 A0R (in), 84 ~{CNTEN}R (in), 85 CLKR (in), 86 ~{ADS}R (in), 87 GND (power), 88 GND (power), 89 ~{ADS}L (in), 90 CLKL (in), 91 ~{CNTEN}L (in), 92 A0L (in), 93 A1L (in), 94 A2L (in), 95 A3L (in), 96 A4L (in), 97 A5L (in), 98 A6L (in), 99 NC, 100 NC

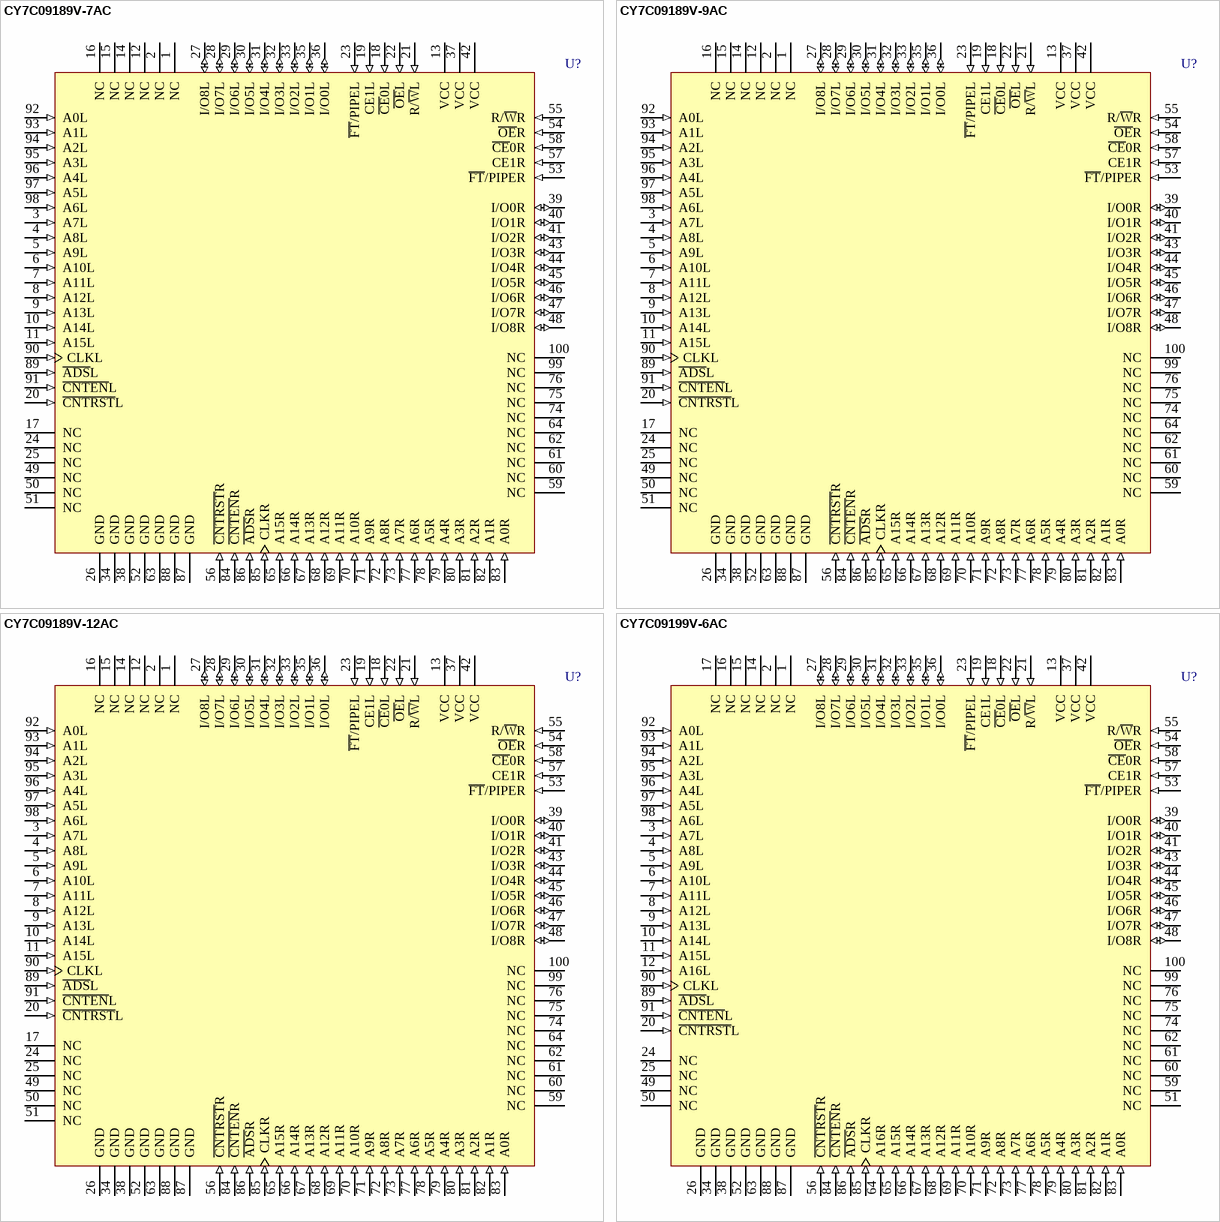
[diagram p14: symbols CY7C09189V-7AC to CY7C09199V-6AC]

## CY7C09189V-7AC
designator U?
3.3V 64K x 9 Synchronous Dual-Port Static RAM
footprint A100_N (Thin QFP, 100-Leads, Body 14x14mm, Pitch 0.5mm, IPC Medium Density)
footprint A100_L (Thin QFP, 100-Leads, Body 14x14mm, Pitch 0.5mm, IPC High Density)
footprint A100_M (Thin QFP, 100-Leads, Body 14x14mm, Pitch 0.5mm, IPC Low Density)
3D model CY7C09189V-A100 (100-Pin Thin Quad Flat Pack 0.5 mm Pitch)
pins: 1 NC, 2 NC, 3 A7L (in), 4 A8L (in), 5 A9L (in), 6 A10L (in), 7 A11L (in), 8 A12L (in), 9 A13L (in), 10 A14L (in), 11 A15L (in), 12 NC, 13 VCC (power), 14 NC, 15 NC, 16 NC, 17 NC, 18 ~{CE}0L (in), 19 CE1L (in), 20 ~{CNTRST}L (in), 21 R/~{W}L (in), 22 ~{OE}L (in), 23 ~{FT}/PIPEL (in), 24 NC, 25 NC, 26 GND (power), 27 I/O8L (io), 28 I/O7L (io), 29 I/O6L (io), 30 I/O5L (io), 31 I/O4L (io), 32 I/O3L (io), 33 I/O2L (io), 34 GND (power), 35 I/O1L (io), 36 I/O0L (io), 37 VCC (power), 38 GND (power), 39 I/O0R (io), 40 I/O1R (io), 41 I/O2R (io), 42 VCC (power), 43 I/O3R (io), 44 I/O4R (io), 45 I/O5R (io), 46 I/O6R (io), 47 I/O7R (io), 48 I/O8R (io), 49 NC, 50 NC, 51 NC, 52 GND (power), 53 ~{FT}/PIPER (in), 54 ~{OE}R (in), 55 R/~{W}R (in), 56 ~{CNTRST}R (in), 57 CE1R (in), 58 ~{CE}0R (in), 59 NC, 60 NC, 61 NC, 62 NC, 63 GND (power), 64 NC, 65 A15R (in), 66 A14R (in), 67 A13R (in), 68 A12R (in), 69 A11R (in), 70 A10R (in), 71 A9R (in), 72 A8R (in), 73 A7R (in), 74 NC, 75 NC, 76 NC, 77 A6R (in), 78 A5R (in), 79 A4R (in), 80 A3R (in), 81 A2R (in), 82 A1R (in), 83 A0R (in), 84 ~{CNTEN}R (in), 85 CLKR (in), 86 ~{ADS}R (in), 87 GND (power), 88 GND (power), 89 ~{ADS}L (in), 90 CLKL (in), 91 ~{CNTEN}L (in), 92 A0L (in), 93 A1L (in), 94 A2L (in), 95 A3L (in), 96 A4L (in), 97 A5L (in), 98 A6L (in), 99 NC, 100 NC

## CY7C09189V-9AC
designator U?
3.3V 64K x 9 Synchronous Dual-Port Static RAM
footprint A100_N (Thin QFP, 100-Leads, Body 14x14mm, Pitch 0.5mm, IPC Medium Density)
footprint A100_L (Thin QFP, 100-Leads, Body 14x14mm, Pitch 0.5mm, IPC High Density)
footprint A100_M (Thin QFP, 100-Leads, Body 14x14mm, Pitch 0.5mm, IPC Low Density)
3D model CY7C09189V-A100 (100-Pin Thin Quad Flat Pack 0.5 mm Pitch)
pins: 1 NC, 2 NC, 3 A7L (in), 4 A8L (in), 5 A9L (in), 6 A10L (in), 7 A11L (in), 8 A12L (in), 9 A13L (in), 10 A14L (in), 11 A15L (in), 12 NC, 13 VCC (power), 14 NC, 15 NC, 16 NC, 17 NC, 18 ~{CE}0L (in), 19 CE1L (in), 20 ~{CNTRST}L (in), 21 R/~{W}L (in), 22 ~{OE}L (in), 23 ~{FT}/PIPEL (in), 24 NC, 25 NC, 26 GND (power), 27 I/O8L (io), 28 I/O7L (io), 29 I/O6L (io), 30 I/O5L (io), 31 I/O4L (io), 32 I/O3L (io), 33 I/O2L (io), 34 GND (power), 35 I/O1L (io), 36 I/O0L (io), 37 VCC (power), 38 GND (power), 39 I/O0R (io), 40 I/O1R (io), 41 I/O2R (io), 42 VCC (power), 43 I/O3R (io), 44 I/O4R (io), 45 I/O5R (io), 46 I/O6R (io), 47 I/O7R (io), 48 I/O8R (io), 49 NC, 50 NC, 51 NC, 52 GND (power), 53 ~{FT}/PIPER (in), 54 ~{OE}R (in), 55 R/~{W}R (in), 56 ~{CNTRST}R (in), 57 CE1R (in), 58 ~{CE}0R (in), 59 NC, 60 NC, 61 NC, 62 NC, 63 GND (power), 64 NC, 65 A15R (in), 66 A14R (in), 67 A13R (in), 68 A12R (in), 69 A11R (in), 70 A10R (in), 71 A9R (in), 72 A8R (in), 73 A7R (in), 74 NC, 75 NC, 76 NC, 77 A6R (in), 78 A5R (in), 79 A4R (in), 80 A3R (in), 81 A2R (in), 82 A1R (in), 83 A0R (in), 84 ~{CNTEN}R (in), 85 CLKR (in), 86 ~{ADS}R (in), 87 GND (power), 88 GND (power), 89 ~{ADS}L (in), 90 CLKL (in), 91 ~{CNTEN}L (in), 92 A0L (in), 93 A1L (in), 94 A2L (in), 95 A3L (in), 96 A4L (in), 97 A5L (in), 98 A6L (in), 99 NC, 100 NC

## CY7C09189V-12AC
designator U?
3.3V 64K x 9 Synchronous Dual-Port Static RAM
footprint A100_N (Thin QFP, 100-Leads, Body 14x14mm, Pitch 0.5mm, IPC Medium Density)
footprint A100_L (Thin QFP, 100-Leads, Body 14x14mm, Pitch 0.5mm, IPC High Density)
footprint A100_M (Thin QFP, 100-Leads, Body 14x14mm, Pitch 0.5mm, IPC Low Density)
3D model CY7C09189V-A100 (100-Pin Thin Quad Flat Pack 0.5 mm Pitch)
pins: 1 NC, 2 NC, 3 A7L (in), 4 A8L (in), 5 A9L (in), 6 A10L (in), 7 A11L (in), 8 A12L (in), 9 A13L (in), 10 A14L (in), 11 A15L (in), 12 NC, 13 VCC (power), 14 NC, 15 NC, 16 NC, 17 NC, 18 ~{CE}0L (in), 19 CE1L (in), 20 ~{CNTRST}L (in), 21 R/~{W}L (in), 22 ~{OE}L (in), 23 ~{FT}/PIPEL (in), 24 NC, 25 NC, 26 GND (power), 27 I/O8L (io), 28 I/O7L (io), 29 I/O6L (io), 30 I/O5L (io), 31 I/O4L (io), 32 I/O3L (io), 33 I/O2L (io), 34 GND (power), 35 I/O1L (io), 36 I/O0L (io), 37 VCC (power), 38 GND (power), 39 I/O0R (io), 40 I/O1R (io), 41 I/O2R (io), 42 VCC (power), 43 I/O3R (io), 44 I/O4R (io), 45 I/O5R (io), 46 I/O6R (io), 47 I/O7R (io), 48 I/O8R (io), 49 NC, 50 NC, 51 NC, 52 GND (power), 53 ~{FT}/PIPER (in), 54 ~{OE}R (in), 55 R/~{W}R (in), 56 ~{CNTRST}R (in), 57 CE1R (in), 58 ~{CE}0R (in), 59 NC, 60 NC, 61 NC, 62 NC, 63 GND (power), 64 NC, 65 A15R (in), 66 A14R (in), 67 A13R (in), 68 A12R (in), 69 A11R (in), 70 A10R (in), 71 A9R (in), 72 A8R (in), 73 A7R (in), 74 NC, 75 NC, 76 NC, 77 A6R (in), 78 A5R (in), 79 A4R (in), 80 A3R (in), 81 A2R (in), 82 A1R (in), 83 A0R (in), 84 ~{CNTEN}R (in), 85 CLKR (in), 86 ~{ADS}R (in), 87 GND (power), 88 GND (power), 89 ~{ADS}L (in), 90 CLKL (in), 91 ~{CNTEN}L (in), 92 A0L (in), 93 A1L (in), 94 A2L (in), 95 A3L (in), 96 A4L (in), 97 A5L (in), 98 A6L (in), 99 NC, 100 NC

## CY7C09199V-6AC
designator U?
3.3V 128K x 9 Synchronous Dual-Port Static RAM
footprint A100_N (Thin QFP, 100-Leads, Body 14x14mm, Pitch 0.5mm, IPC Medium Density)
footprint A100_L (Thin QFP, 100-Leads, Body 14x14mm, Pitch 0.5mm, IPC High Density)
footprint A100_M (Thin QFP, 100-Leads, Body 14x14mm, Pitch 0.5mm, IPC Low Density)
3D model CY7C09199V-A100 (100-Pin Thin Quad Flat Pack 0.5 mm Pitch)
pins: 1 NC, 2 NC, 3 A7L (in), 4 A8L (in), 5 A9L (in), 6 A10L (in), 7 A11L (in), 8 A12L (in), 9 A13L (in), 10 A14L (in), 11 A15L (in), 12 A16L (in), 13 VCC (power), 14 NC, 15 NC, 16 NC, 17 NC, 18 ~{CE}0L (in), 19 CE1L (in), 20 ~{CNTRST}L (in), 21 R/~{W}L (in), 22 ~{OE}L (in), 23 ~{FT}/PIPEL (in), 24 NC, 25 NC, 26 GND (power), 27 I/O8L (io), 28 I/O7L (io), 29 I/O6L (io), 30 I/O5L (io), 31 I/O4L (io), 32 I/O3L (io), 33 I/O2L (io), 34 GND (power), 35 I/O1L (io), 36 I/O0L (io), 37 VCC (power), 38 GND (power), 39 I/O0R (io), 40 I/O1R (io), 41 I/O2R (io), 42 VCC (power), 43 I/O3R (io), 44 I/O4R (io), 45 I/O5R (io), 46 I/O6R (io), 47 I/O7R (io), 48 I/O8R (io), 49 NC, 50 NC, 51 NC, 52 GND (power), 53 ~{FT}/PIPER (in), 54 ~{OE}R (in), 55 R/~{W}R (in), 56 ~{CNTRST}R (in), 57 CE1R (in), 58 ~{CE}0R (in), 59 NC, 60 NC, 61 NC, 62 NC, 63 GND (power), 64 A16R (in), 65 A15R (in), 66 A14R (in), 67 A13R (in), 68 A12R (in), 69 A11R (in), 70 A10R (in), 71 A9R (in), 72 A8R (in), 73 A7R (in), 74 NC, 75 NC, 76 NC, 77 A6R (in), 78 A5R (in), 79 A4R (in), 80 A3R (in), 81 A2R (in), 82 A1R (in), 83 A0R (in), 84 ~{CNTEN}R (in), 85 CLKR (in), 86 ~{ADS}R (in), 87 GND (power), 88 GND (power), 89 ~{ADS}L (in), 90 CLKL (in), 91 ~{CNTEN}L (in), 92 A0L (in), 93 A1L (in), 94 A2L (in), 95 A3L (in), 96 A4L (in), 97 A5L (in), 98 A6L (in), 99 NC, 100 NC

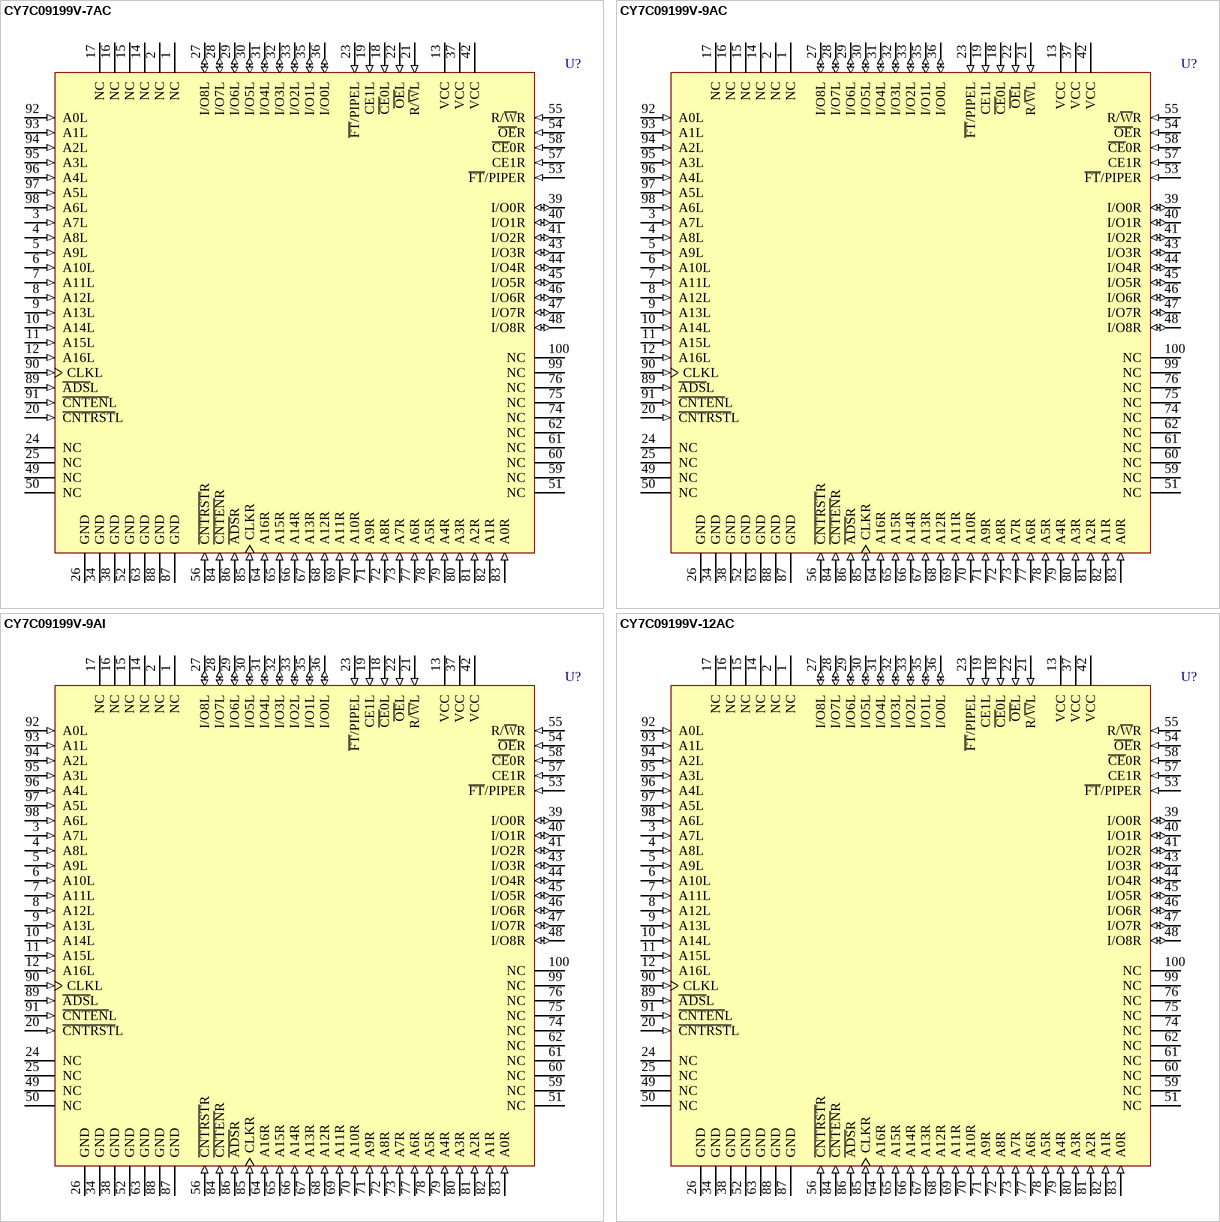
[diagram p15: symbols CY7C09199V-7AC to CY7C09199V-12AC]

## CY7C09199V-7AC
designator U?
3.3V 128K x 9 Synchronous Dual-Port Static RAM
footprint A100_N (Thin QFP, 100-Leads, Body 14x14mm, Pitch 0.5mm, IPC Medium Density)
footprint A100_L (Thin QFP, 100-Leads, Body 14x14mm, Pitch 0.5mm, IPC High Density)
footprint A100_M (Thin QFP, 100-Leads, Body 14x14mm, Pitch 0.5mm, IPC Low Density)
3D model CY7C09199V-A100 (100-Pin Thin Quad Flat Pack 0.5 mm Pitch)
pins: 1 NC, 2 NC, 3 A7L (in), 4 A8L (in), 5 A9L (in), 6 A10L (in), 7 A11L (in), 8 A12L (in), 9 A13L (in), 10 A14L (in), 11 A15L (in), 12 A16L (in), 13 VCC (power), 14 NC, 15 NC, 16 NC, 17 NC, 18 ~{CE}0L (in), 19 CE1L (in), 20 ~{CNTRST}L (in), 21 R/~{W}L (in), 22 ~{OE}L (in), 23 ~{FT}/PIPEL (in), 24 NC, 25 NC, 26 GND (power), 27 I/O8L (io), 28 I/O7L (io), 29 I/O6L (io), 30 I/O5L (io), 31 I/O4L (io), 32 I/O3L (io), 33 I/O2L (io), 34 GND (power), 35 I/O1L (io), 36 I/O0L (io), 37 VCC (power), 38 GND (power), 39 I/O0R (io), 40 I/O1R (io), 41 I/O2R (io), 42 VCC (power), 43 I/O3R (io), 44 I/O4R (io), 45 I/O5R (io), 46 I/O6R (io), 47 I/O7R (io), 48 I/O8R (io), 49 NC, 50 NC, 51 NC, 52 GND (power), 53 ~{FT}/PIPER (in), 54 ~{OE}R (in), 55 R/~{W}R (in), 56 ~{CNTRST}R (in), 57 CE1R (in), 58 ~{CE}0R (in), 59 NC, 60 NC, 61 NC, 62 NC, 63 GND (power), 64 A16R (in), 65 A15R (in), 66 A14R (in), 67 A13R (in), 68 A12R (in), 69 A11R (in), 70 A10R (in), 71 A9R (in), 72 A8R (in), 73 A7R (in), 74 NC, 75 NC, 76 NC, 77 A6R (in), 78 A5R (in), 79 A4R (in), 80 A3R (in), 81 A2R (in), 82 A1R (in), 83 A0R (in), 84 ~{CNTEN}R (in), 85 CLKR (in), 86 ~{ADS}R (in), 87 GND (power), 88 GND (power), 89 ~{ADS}L (in), 90 CLKL (in), 91 ~{CNTEN}L (in), 92 A0L (in), 93 A1L (in), 94 A2L (in), 95 A3L (in), 96 A4L (in), 97 A5L (in), 98 A6L (in), 99 NC, 100 NC

## CY7C09199V-9AC
designator U?
3.3V 128K x 9 Synchronous Dual-Port Static RAM
footprint A100_N (Thin QFP, 100-Leads, Body 14x14mm, Pitch 0.5mm, IPC Medium Density)
footprint A100_L (Thin QFP, 100-Leads, Body 14x14mm, Pitch 0.5mm, IPC High Density)
footprint A100_M (Thin QFP, 100-Leads, Body 14x14mm, Pitch 0.5mm, IPC Low Density)
3D model CY7C09199V-A100 (100-Pin Thin Quad Flat Pack 0.5 mm Pitch)
pins: 1 NC, 2 NC, 3 A7L (in), 4 A8L (in), 5 A9L (in), 6 A10L (in), 7 A11L (in), 8 A12L (in), 9 A13L (in), 10 A14L (in), 11 A15L (in), 12 A16L (in), 13 VCC (power), 14 NC, 15 NC, 16 NC, 17 NC, 18 ~{CE}0L (in), 19 CE1L (in), 20 ~{CNTRST}L (in), 21 R/~{W}L (in), 22 ~{OE}L (in), 23 ~{FT}/PIPEL (in), 24 NC, 25 NC, 26 GND (power), 27 I/O8L (io), 28 I/O7L (io), 29 I/O6L (io), 30 I/O5L (io), 31 I/O4L (io), 32 I/O3L (io), 33 I/O2L (io), 34 GND (power), 35 I/O1L (io), 36 I/O0L (io), 37 VCC (power), 38 GND (power), 39 I/O0R (io), 40 I/O1R (io), 41 I/O2R (io), 42 VCC (power), 43 I/O3R (io), 44 I/O4R (io), 45 I/O5R (io), 46 I/O6R (io), 47 I/O7R (io), 48 I/O8R (io), 49 NC, 50 NC, 51 NC, 52 GND (power), 53 ~{FT}/PIPER (in), 54 ~{OE}R (in), 55 R/~{W}R (in), 56 ~{CNTRST}R (in), 57 CE1R (in), 58 ~{CE}0R (in), 59 NC, 60 NC, 61 NC, 62 NC, 63 GND (power), 64 A16R (in), 65 A15R (in), 66 A14R (in), 67 A13R (in), 68 A12R (in), 69 A11R (in), 70 A10R (in), 71 A9R (in), 72 A8R (in), 73 A7R (in), 74 NC, 75 NC, 76 NC, 77 A6R (in), 78 A5R (in), 79 A4R (in), 80 A3R (in), 81 A2R (in), 82 A1R (in), 83 A0R (in), 84 ~{CNTEN}R (in), 85 CLKR (in), 86 ~{ADS}R (in), 87 GND (power), 88 GND (power), 89 ~{ADS}L (in), 90 CLKL (in), 91 ~{CNTEN}L (in), 92 A0L (in), 93 A1L (in), 94 A2L (in), 95 A3L (in), 96 A4L (in), 97 A5L (in), 98 A6L (in), 99 NC, 100 NC

## CY7C09199V-9AI
designator U?
3.3V 128K x 9 Synchronous Dual-Port Static RAM
footprint A100_N (Thin QFP, 100-Leads, Body 14x14mm, Pitch 0.5mm, IPC Medium Density)
footprint A100_L (Thin QFP, 100-Leads, Body 14x14mm, Pitch 0.5mm, IPC High Density)
footprint A100_M (Thin QFP, 100-Leads, Body 14x14mm, Pitch 0.5mm, IPC Low Density)
3D model CY7C09199V-A100 (100-Pin Thin Quad Flat Pack 0.5 mm Pitch)
pins: 1 NC, 2 NC, 3 A7L (in), 4 A8L (in), 5 A9L (in), 6 A10L (in), 7 A11L (in), 8 A12L (in), 9 A13L (in), 10 A14L (in), 11 A15L (in), 12 A16L (in), 13 VCC (power), 14 NC, 15 NC, 16 NC, 17 NC, 18 ~{CE}0L (in), 19 CE1L (in), 20 ~{CNTRST}L (in), 21 R/~{W}L (in), 22 ~{OE}L (in), 23 ~{FT}/PIPEL (in), 24 NC, 25 NC, 26 GND (power), 27 I/O8L (io), 28 I/O7L (io), 29 I/O6L (io), 30 I/O5L (io), 31 I/O4L (io), 32 I/O3L (io), 33 I/O2L (io), 34 GND (power), 35 I/O1L (io), 36 I/O0L (io), 37 VCC (power), 38 GND (power), 39 I/O0R (io), 40 I/O1R (io), 41 I/O2R (io), 42 VCC (power), 43 I/O3R (io), 44 I/O4R (io), 45 I/O5R (io), 46 I/O6R (io), 47 I/O7R (io), 48 I/O8R (io), 49 NC, 50 NC, 51 NC, 52 GND (power), 53 ~{FT}/PIPER (in), 54 ~{OE}R (in), 55 R/~{W}R (in), 56 ~{CNTRST}R (in), 57 CE1R (in), 58 ~{CE}0R (in), 59 NC, 60 NC, 61 NC, 62 NC, 63 GND (power), 64 A16R (in), 65 A15R (in), 66 A14R (in), 67 A13R (in), 68 A12R (in), 69 A11R (in), 70 A10R (in), 71 A9R (in), 72 A8R (in), 73 A7R (in), 74 NC, 75 NC, 76 NC, 77 A6R (in), 78 A5R (in), 79 A4R (in), 80 A3R (in), 81 A2R (in), 82 A1R (in), 83 A0R (in), 84 ~{CNTEN}R (in), 85 CLKR (in), 86 ~{ADS}R (in), 87 GND (power), 88 GND (power), 89 ~{ADS}L (in), 90 CLKL (in), 91 ~{CNTEN}L (in), 92 A0L (in), 93 A1L (in), 94 A2L (in), 95 A3L (in), 96 A4L (in), 97 A5L (in), 98 A6L (in), 99 NC, 100 NC

## CY7C09199V-12AC
designator U?
3.3V 128K x 9 Synchronous Dual-Port Static RAM
footprint A100_N (Thin QFP, 100-Leads, Body 14x14mm, Pitch 0.5mm, IPC Medium Density)
footprint A100_L (Thin QFP, 100-Leads, Body 14x14mm, Pitch 0.5mm, IPC High Density)
footprint A100_M (Thin QFP, 100-Leads, Body 14x14mm, Pitch 0.5mm, IPC Low Density)
3D model CY7C09199V-A100 (100-Pin Thin Quad Flat Pack 0.5 mm Pitch)
pins: 1 NC, 2 NC, 3 A7L (in), 4 A8L (in), 5 A9L (in), 6 A10L (in), 7 A11L (in), 8 A12L (in), 9 A13L (in), 10 A14L (in), 11 A15L (in), 12 A16L (in), 13 VCC (power), 14 NC, 15 NC, 16 NC, 17 NC, 18 ~{CE}0L (in), 19 CE1L (in), 20 ~{CNTRST}L (in), 21 R/~{W}L (in), 22 ~{OE}L (in), 23 ~{FT}/PIPEL (in), 24 NC, 25 NC, 26 GND (power), 27 I/O8L (io), 28 I/O7L (io), 29 I/O6L (io), 30 I/O5L (io), 31 I/O4L (io), 32 I/O3L (io), 33 I/O2L (io), 34 GND (power), 35 I/O1L (io), 36 I/O0L (io), 37 VCC (power), 38 GND (power), 39 I/O0R (io), 40 I/O1R (io), 41 I/O2R (io), 42 VCC (power), 43 I/O3R (io), 44 I/O4R (io), 45 I/O5R (io), 46 I/O6R (io), 47 I/O7R (io), 48 I/O8R (io), 49 NC, 50 NC, 51 NC, 52 GND (power), 53 ~{FT}/PIPER (in), 54 ~{OE}R (in), 55 R/~{W}R (in), 56 ~{CNTRST}R (in), 57 CE1R (in), 58 ~{CE}0R (in), 59 NC, 60 NC, 61 NC, 62 NC, 63 GND (power), 64 A16R (in), 65 A15R (in), 66 A14R (in), 67 A13R (in), 68 A12R (in), 69 A11R (in), 70 A10R (in), 71 A9R (in), 72 A8R (in), 73 A7R (in), 74 NC, 75 NC, 76 NC, 77 A6R (in), 78 A5R (in), 79 A4R (in), 80 A3R (in), 81 A2R (in), 82 A1R (in), 83 A0R (in), 84 ~{CNTEN}R (in), 85 CLKR (in), 86 ~{ADS}R (in), 87 GND (power), 88 GND (power), 89 ~{ADS}L (in), 90 CLKL (in), 91 ~{CNTEN}L (in), 92 A0L (in), 93 A1L (in), 94 A2L (in), 95 A3L (in), 96 A4L (in), 97 A5L (in), 98 A6L (in), 99 NC, 100 NC

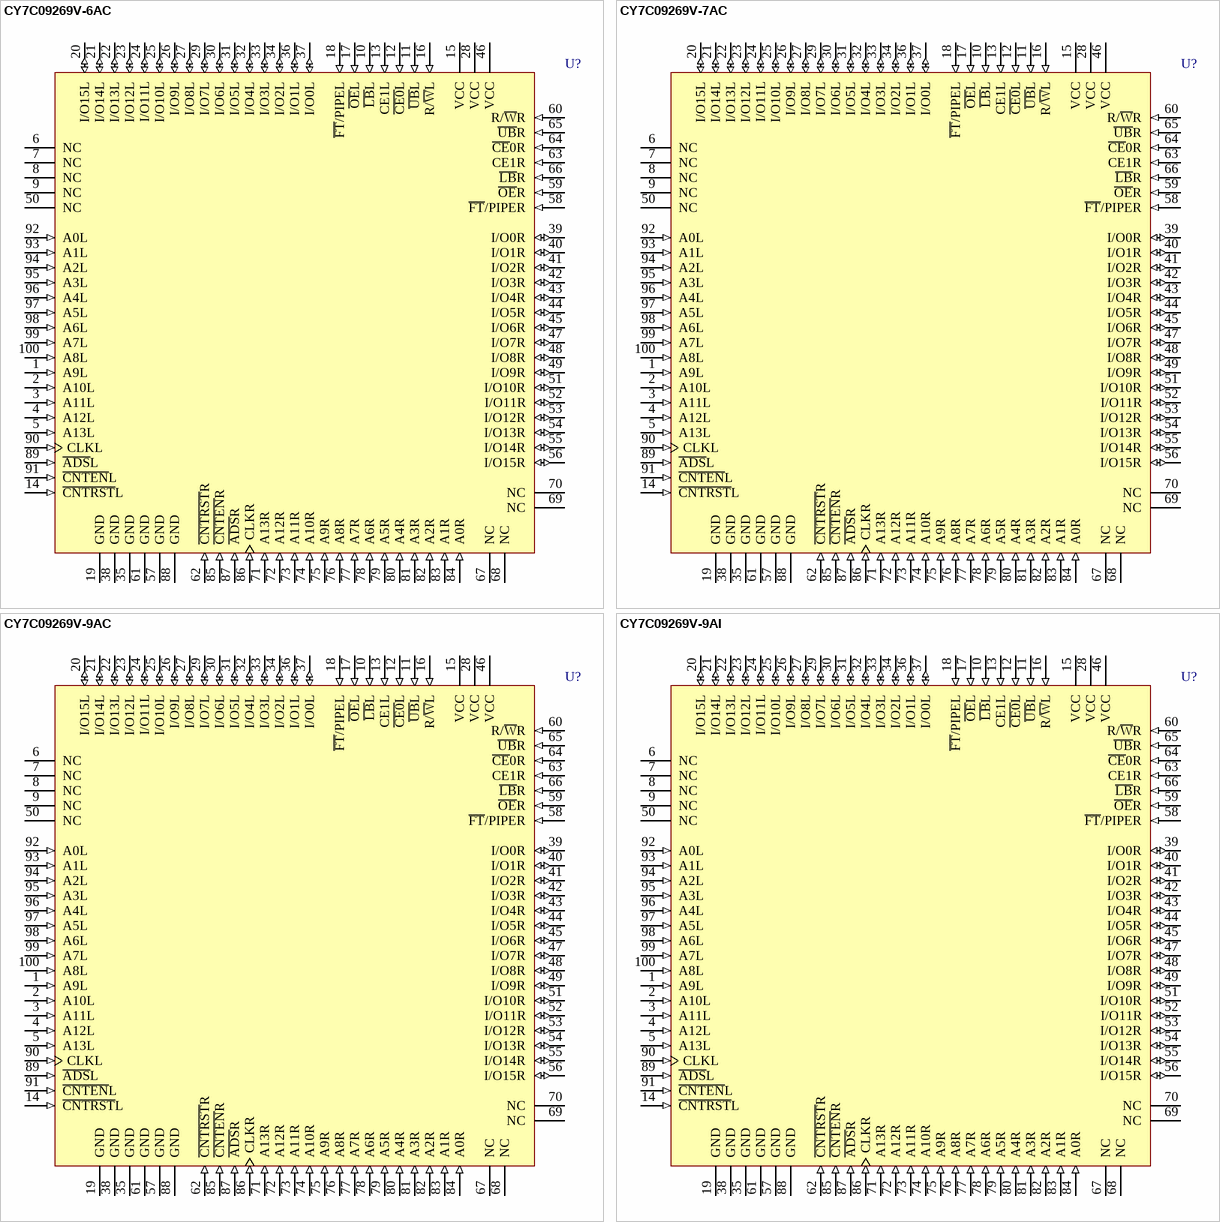
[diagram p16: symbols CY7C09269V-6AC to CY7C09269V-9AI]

## CY7C09269V-6AC
designator U?
3.3V 16K x 16 Synchronous Dual-Port Static RAM
footprint A100_N (Thin QFP, 100-Leads, Body 14x14mm, Pitch 0.5mm, IPC Medium Density)
footprint A100_L (Thin QFP, 100-Leads, Body 14x14mm, Pitch 0.5mm, IPC High Density)
footprint A100_M (Thin QFP, 100-Leads, Body 14x14mm, Pitch 0.5mm, IPC Low Density)
3D model CY7C09269V-A100 (100-Pin Thin Quad Flat Pack 0.5 mm Pitch)
pins: 1 A9L (in), 2 A10L (in), 3 A11L (in), 4 A12L (in), 5 A13L (in), 6 NC, 7 NC, 8 NC, 9 NC, 10 ~{LB}L (in), 11 ~{UB}L (in), 12 ~{CE0}L (in), 13 CE1L (in), 14 ~{CNTRST}L (in), 15 VCC (power), 16 R/~{W}L (in), 17 ~{OE}L (in), 18 ~{FT}/PIPEL (in), 19 GND (power), 20 I/O15L (io), 21 I/O14L (io), 22 I/O13L (io), 23 I/O12L (io), 24 I/O11L (io), 25 I/O10L (io), 26 I/O9L (io), 27 I/O8L (io), 28 VCC (power), 29 I/O7L (io), 30 I/O6L (io), 31 I/O5L (io), 32 I/O4L (io), 33 I/O3L (io), 34 I/O2L (io), 35 GND (power), 36 I/O1L (io), 37 I/O0L (io), 38 GND (power), 39 I/O0R (io), 40 I/O1R (io), 41 I/O2R (io), 42 I/O3R (io), 43 I/O4R (io), 44 I/O5R (io), 45 I/O6R (io), 46 VCC (power), 47 I/O7R (io), 48 I/O8R (io), 49 I/O9R (io), 50 NC, 51 I/O10R (io), 52 I/O11R (io), 53 I/O12R (io), 54 I/O13R (io), 55 I/O14R (io), 56 I/O15R (io), 57 GND (power), 58 ~{FT}/PIPER (in), 59 ~{OE}R (in), 60 R/~{W}R (in), 61 GND (power), 62 ~{CNTRST}R (in), 63 CE1R (in), 64 ~{CE}0R (in), 65 ~{UB}R (in), 66 ~{LB}R (in), 67 NC, 68 NC, 69 NC, 70 NC, 71 A13R (in), 72 A12R (in), 73 A11R (in), 74 A10R (in), 75 A9R (in), 76 A8R (in), 77 A7R (in), 78 A6R (in), 79 A5R (in), 80 A4R (in), 81 A3R (in), 82 A2R (in), 83 A1R (in), 84 A0R (in), 85 ~{CNTEN}R (in), 86 CLKR (in), 87 ~{ADS}R (in), 88 GND (power), 89 ~{ADS}L (in), 90 CLKL (in), 91 ~{CNTEN}L (in), 92 A0L (in), 93 A1L (in), 94 A2L (in), 95 A3L (in), 96 A4L (in), 97 A5L (in), 98 A6L (in), 99 A7L (in), 100 A8L (in)

## CY7C09269V-7AC
designator U?
3.3V 16K x 16 Synchronous Dual-Port Static RAM
footprint A100_N (Thin QFP, 100-Leads, Body 14x14mm, Pitch 0.5mm, IPC Medium Density)
footprint A100_L (Thin QFP, 100-Leads, Body 14x14mm, Pitch 0.5mm, IPC High Density)
footprint A100_M (Thin QFP, 100-Leads, Body 14x14mm, Pitch 0.5mm, IPC Low Density)
3D model CY7C09269V-A100 (100-Pin Thin Quad Flat Pack 0.5 mm Pitch)
pins: 1 A9L (in), 2 A10L (in), 3 A11L (in), 4 A12L (in), 5 A13L (in), 6 NC, 7 NC, 8 NC, 9 NC, 10 ~{LB}L (in), 11 ~{UB}L (in), 12 ~{CE0}L (in), 13 CE1L (in), 14 ~{CNTRST}L (in), 15 VCC (power), 16 R/~{W}L (in), 17 ~{OE}L (in), 18 ~{FT}/PIPEL (in), 19 GND (power), 20 I/O15L (io), 21 I/O14L (io), 22 I/O13L (io), 23 I/O12L (io), 24 I/O11L (io), 25 I/O10L (io), 26 I/O9L (io), 27 I/O8L (io), 28 VCC (power), 29 I/O7L (io), 30 I/O6L (io), 31 I/O5L (io), 32 I/O4L (io), 33 I/O3L (io), 34 I/O2L (io), 35 GND (power), 36 I/O1L (io), 37 I/O0L (io), 38 GND (power), 39 I/O0R (io), 40 I/O1R (io), 41 I/O2R (io), 42 I/O3R (io), 43 I/O4R (io), 44 I/O5R (io), 45 I/O6R (io), 46 VCC (power), 47 I/O7R (io), 48 I/O8R (io), 49 I/O9R (io), 50 NC, 51 I/O10R (io), 52 I/O11R (io), 53 I/O12R (io), 54 I/O13R (io), 55 I/O14R (io), 56 I/O15R (io), 57 GND (power), 58 ~{FT}/PIPER (in), 59 ~{OE}R (in), 60 R/~{W}R (in), 61 GND (power), 62 ~{CNTRST}R (in), 63 CE1R (in), 64 ~{CE}0R (in), 65 ~{UB}R (in), 66 ~{LB}R (in), 67 NC, 68 NC, 69 NC, 70 NC, 71 A13R (in), 72 A12R (in), 73 A11R (in), 74 A10R (in), 75 A9R (in), 76 A8R (in), 77 A7R (in), 78 A6R (in), 79 A5R (in), 80 A4R (in), 81 A3R (in), 82 A2R (in), 83 A1R (in), 84 A0R (in), 85 ~{CNTEN}R (in), 86 CLKR (in), 87 ~{ADS}R (in), 88 GND (power), 89 ~{ADS}L (in), 90 CLKL (in), 91 ~{CNTEN}L (in), 92 A0L (in), 93 A1L (in), 94 A2L (in), 95 A3L (in), 96 A4L (in), 97 A5L (in), 98 A6L (in), 99 A7L (in), 100 A8L (in)

## CY7C09269V-9AC
designator U?
3.3V 16K x 16 Synchronous Dual-Port Static RAM
footprint A100_N (Thin QFP, 100-Leads, Body 14x14mm, Pitch 0.5mm, IPC Medium Density)
footprint A100_L (Thin QFP, 100-Leads, Body 14x14mm, Pitch 0.5mm, IPC High Density)
footprint A100_M (Thin QFP, 100-Leads, Body 14x14mm, Pitch 0.5mm, IPC Low Density)
3D model CY7C09269V-A100 (100-Pin Thin Quad Flat Pack 0.5 mm Pitch)
pins: 1 A9L (in), 2 A10L (in), 3 A11L (in), 4 A12L (in), 5 A13L (in), 6 NC, 7 NC, 8 NC, 9 NC, 10 ~{LB}L (in), 11 ~{UB}L (in), 12 ~{CE0}L (in), 13 CE1L (in), 14 ~{CNTRST}L (in), 15 VCC (power), 16 R/~{W}L (in), 17 ~{OE}L (in), 18 ~{FT}/PIPEL (in), 19 GND (power), 20 I/O15L (io), 21 I/O14L (io), 22 I/O13L (io), 23 I/O12L (io), 24 I/O11L (io), 25 I/O10L (io), 26 I/O9L (io), 27 I/O8L (io), 28 VCC (power), 29 I/O7L (io), 30 I/O6L (io), 31 I/O5L (io), 32 I/O4L (io), 33 I/O3L (io), 34 I/O2L (io), 35 GND (power), 36 I/O1L (io), 37 I/O0L (io), 38 GND (power), 39 I/O0R (io), 40 I/O1R (io), 41 I/O2R (io), 42 I/O3R (io), 43 I/O4R (io), 44 I/O5R (io), 45 I/O6R (io), 46 VCC (power), 47 I/O7R (io), 48 I/O8R (io), 49 I/O9R (io), 50 NC, 51 I/O10R (io), 52 I/O11R (io), 53 I/O12R (io), 54 I/O13R (io), 55 I/O14R (io), 56 I/O15R (io), 57 GND (power), 58 ~{FT}/PIPER (in), 59 ~{OE}R (in), 60 R/~{W}R (in), 61 GND (power), 62 ~{CNTRST}R (in), 63 CE1R (in), 64 ~{CE}0R (in), 65 ~{UB}R (in), 66 ~{LB}R (in), 67 NC, 68 NC, 69 NC, 70 NC, 71 A13R (in), 72 A12R (in), 73 A11R (in), 74 A10R (in), 75 A9R (in), 76 A8R (in), 77 A7R (in), 78 A6R (in), 79 A5R (in), 80 A4R (in), 81 A3R (in), 82 A2R (in), 83 A1R (in), 84 A0R (in), 85 ~{CNTEN}R (in), 86 CLKR (in), 87 ~{ADS}R (in), 88 GND (power), 89 ~{ADS}L (in), 90 CLKL (in), 91 ~{CNTEN}L (in), 92 A0L (in), 93 A1L (in), 94 A2L (in), 95 A3L (in), 96 A4L (in), 97 A5L (in), 98 A6L (in), 99 A7L (in), 100 A8L (in)

## CY7C09269V-9AI
designator U?
3.3V 16K x 16 Synchronous Dual-Port Static RAM
footprint A100_N (Thin QFP, 100-Leads, Body 14x14mm, Pitch 0.5mm, IPC Medium Density)
footprint A100_L (Thin QFP, 100-Leads, Body 14x14mm, Pitch 0.5mm, IPC High Density)
footprint A100_M (Thin QFP, 100-Leads, Body 14x14mm, Pitch 0.5mm, IPC Low Density)
3D model CY7C09269V-A100 (100-Pin Thin Quad Flat Pack 0.5 mm Pitch)
pins: 1 A9L (in), 2 A10L (in), 3 A11L (in), 4 A12L (in), 5 A13L (in), 6 NC, 7 NC, 8 NC, 9 NC, 10 ~{LB}L (in), 11 ~{UB}L (in), 12 ~{CE0}L (in), 13 CE1L (in), 14 ~{CNTRST}L (in), 15 VCC (power), 16 R/~{W}L (in), 17 ~{OE}L (in), 18 ~{FT}/PIPEL (in), 19 GND (power), 20 I/O15L (io), 21 I/O14L (io), 22 I/O13L (io), 23 I/O12L (io), 24 I/O11L (io), 25 I/O10L (io), 26 I/O9L (io), 27 I/O8L (io), 28 VCC (power), 29 I/O7L (io), 30 I/O6L (io), 31 I/O5L (io), 32 I/O4L (io), 33 I/O3L (io), 34 I/O2L (io), 35 GND (power), 36 I/O1L (io), 37 I/O0L (io), 38 GND (power), 39 I/O0R (io), 40 I/O1R (io), 41 I/O2R (io), 42 I/O3R (io), 43 I/O4R (io), 44 I/O5R (io), 45 I/O6R (io), 46 VCC (power), 47 I/O7R (io), 48 I/O8R (io), 49 I/O9R (io), 50 NC, 51 I/O10R (io), 52 I/O11R (io), 53 I/O12R (io), 54 I/O13R (io), 55 I/O14R (io), 56 I/O15R (io), 57 GND (power), 58 ~{FT}/PIPER (in), 59 ~{OE}R (in), 60 R/~{W}R (in), 61 GND (power), 62 ~{CNTRST}R (in), 63 CE1R (in), 64 ~{CE}0R (in), 65 ~{UB}R (in), 66 ~{LB}R (in), 67 NC, 68 NC, 69 NC, 70 NC, 71 A13R (in), 72 A12R (in), 73 A11R (in), 74 A10R (in), 75 A9R (in), 76 A8R (in), 77 A7R (in), 78 A6R (in), 79 A5R (in), 80 A4R (in), 81 A3R (in), 82 A2R (in), 83 A1R (in), 84 A0R (in), 85 ~{CNTEN}R (in), 86 CLKR (in), 87 ~{ADS}R (in), 88 GND (power), 89 ~{ADS}L (in), 90 CLKL (in), 91 ~{CNTEN}L (in), 92 A0L (in), 93 A1L (in), 94 A2L (in), 95 A3L (in), 96 A4L (in), 97 A5L (in), 98 A6L (in), 99 A7L (in), 100 A8L (in)

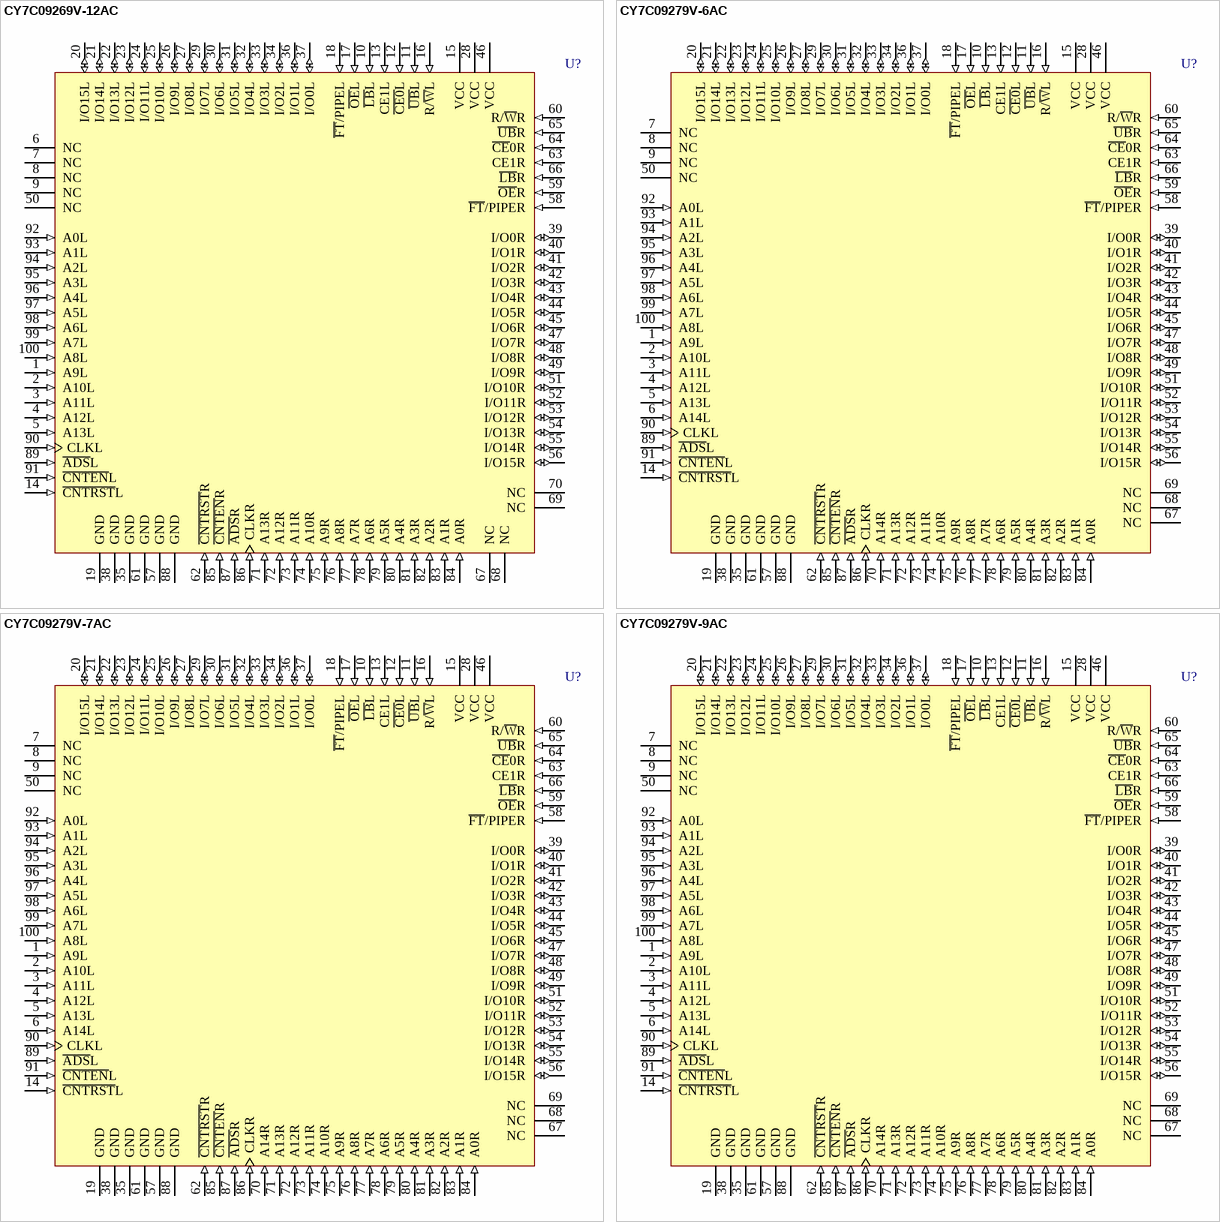
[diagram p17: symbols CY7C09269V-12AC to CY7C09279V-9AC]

## CY7C09269V-12AC
designator U?
3.3V 16K x 16 Synchronous Dual-Port Static RAM
footprint A100_N (Thin QFP, 100-Leads, Body 14x14mm, Pitch 0.5mm, IPC Medium Density)
footprint A100_L (Thin QFP, 100-Leads, Body 14x14mm, Pitch 0.5mm, IPC High Density)
footprint A100_M (Thin QFP, 100-Leads, Body 14x14mm, Pitch 0.5mm, IPC Low Density)
3D model CY7C09269V-A100 (100-Pin Thin Quad Flat Pack 0.5 mm Pitch)
pins: 1 A9L (in), 2 A10L (in), 3 A11L (in), 4 A12L (in), 5 A13L (in), 6 NC, 7 NC, 8 NC, 9 NC, 10 ~{LB}L (in), 11 ~{UB}L (in), 12 ~{CE0}L (in), 13 CE1L (in), 14 ~{CNTRST}L (in), 15 VCC (power), 16 R/~{W}L (in), 17 ~{OE}L (in), 18 ~{FT}/PIPEL (in), 19 GND (power), 20 I/O15L (io), 21 I/O14L (io), 22 I/O13L (io), 23 I/O12L (io), 24 I/O11L (io), 25 I/O10L (io), 26 I/O9L (io), 27 I/O8L (io), 28 VCC (power), 29 I/O7L (io), 30 I/O6L (io), 31 I/O5L (io), 32 I/O4L (io), 33 I/O3L (io), 34 I/O2L (io), 35 GND (power), 36 I/O1L (io), 37 I/O0L (io), 38 GND (power), 39 I/O0R (io), 40 I/O1R (io), 41 I/O2R (io), 42 I/O3R (io), 43 I/O4R (io), 44 I/O5R (io), 45 I/O6R (io), 46 VCC (power), 47 I/O7R (io), 48 I/O8R (io), 49 I/O9R (io), 50 NC, 51 I/O10R (io), 52 I/O11R (io), 53 I/O12R (io), 54 I/O13R (io), 55 I/O14R (io), 56 I/O15R (io), 57 GND (power), 58 ~{FT}/PIPER (in), 59 ~{OE}R (in), 60 R/~{W}R (in), 61 GND (power), 62 ~{CNTRST}R (in), 63 CE1R (in), 64 ~{CE}0R (in), 65 ~{UB}R (in), 66 ~{LB}R (in), 67 NC, 68 NC, 69 NC, 70 NC, 71 A13R (in), 72 A12R (in), 73 A11R (in), 74 A10R (in), 75 A9R (in), 76 A8R (in), 77 A7R (in), 78 A6R (in), 79 A5R (in), 80 A4R (in), 81 A3R (in), 82 A2R (in), 83 A1R (in), 84 A0R (in), 85 ~{CNTEN}R (in), 86 CLKR (in), 87 ~{ADS}R (in), 88 GND (power), 89 ~{ADS}L (in), 90 CLKL (in), 91 ~{CNTEN}L (in), 92 A0L (in), 93 A1L (in), 94 A2L (in), 95 A3L (in), 96 A4L (in), 97 A5L (in), 98 A6L (in), 99 A7L (in), 100 A8L (in)

## CY7C09279V-6AC
designator U?
3.3V 32K x 16 Synchronous Dual-Port Static RAM
footprint A100_N (Thin QFP, 100-Leads, Body 14x14mm, Pitch 0.5mm, IPC Medium Density)
footprint A100_L (Thin QFP, 100-Leads, Body 14x14mm, Pitch 0.5mm, IPC High Density)
footprint A100_M (Thin QFP, 100-Leads, Body 14x14mm, Pitch 0.5mm, IPC Low Density)
3D model CY7C09279V-A100 (100-Pin Thin Quad Flat Pack 0.5 mm Pitch)
pins: 1 A9L (in), 2 A10L (in), 3 A11L (in), 4 A12L (in), 5 A13L (in), 6 A14L (in), 7 NC, 8 NC, 9 NC, 10 ~{LB}L (in), 11 ~{UB}L (in), 12 ~{CE0}L (in), 13 CE1L (in), 14 ~{CNTRST}L (in), 15 VCC (power), 16 R/~{W}L (in), 17 ~{OE}L (in), 18 ~{FT}/PIPEL (in), 19 GND (power), 20 I/O15L (io), 21 I/O14L (io), 22 I/O13L (io), 23 I/O12L (io), 24 I/O11L (io), 25 I/O10L (io), 26 I/O9L (io), 27 I/O8L (io), 28 VCC (power), 29 I/O7L (io), 30 I/O6L (io), 31 I/O5L (io), 32 I/O4L (io), 33 I/O3L (io), 34 I/O2L (io), 35 GND (power), 36 I/O1L (io), 37 I/O0L (io), 38 GND (power), 39 I/O0R (io), 40 I/O1R (io), 41 I/O2R (io), 42 I/O3R (io), 43 I/O4R (io), 44 I/O5R (io), 45 I/O6R (io), 46 VCC (power), 47 I/O7R (io), 48 I/O8R (io), 49 I/O9R (io), 50 NC, 51 I/O10R (io), 52 I/O11R (io), 53 I/O12R (io), 54 I/O13R (io), 55 I/O14R (io), 56 I/O15R (io), 57 GND (power), 58 ~{FT}/PIPER (in), 59 ~{OE}R (in), 60 R/~{W}R (in), 61 GND (power), 62 ~{CNTRST}R (in), 63 CE1R (in), 64 ~{CE}0R (in), 65 ~{UB}R (in), 66 ~{LB}R (in), 67 NC, 68 NC, 69 NC, 70 A14R (in), 71 A13R (in), 72 A12R (in), 73 A11R (in), 74 A10R (in), 75 A9R (in), 76 A8R (in), 77 A7R (in), 78 A6R (in), 79 A5R (in), 80 A4R (in), 81 A3R (in), 82 A2R (in), 83 A1R (in), 84 A0R (in), 85 ~{CNTEN}R (in), 86 CLKR (in), 87 ~{ADS}R (in), 88 GND (power), 89 ~{ADS}L (in), 90 CLKL (in), 91 ~{CNTEN}L (in), 92 A0L (in), 93 A1L (in), 94 A2L (in), 95 A3L (in), 96 A4L (in), 97 A5L (in), 98 A6L (in), 99 A7L (in), 100 A8L (in)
